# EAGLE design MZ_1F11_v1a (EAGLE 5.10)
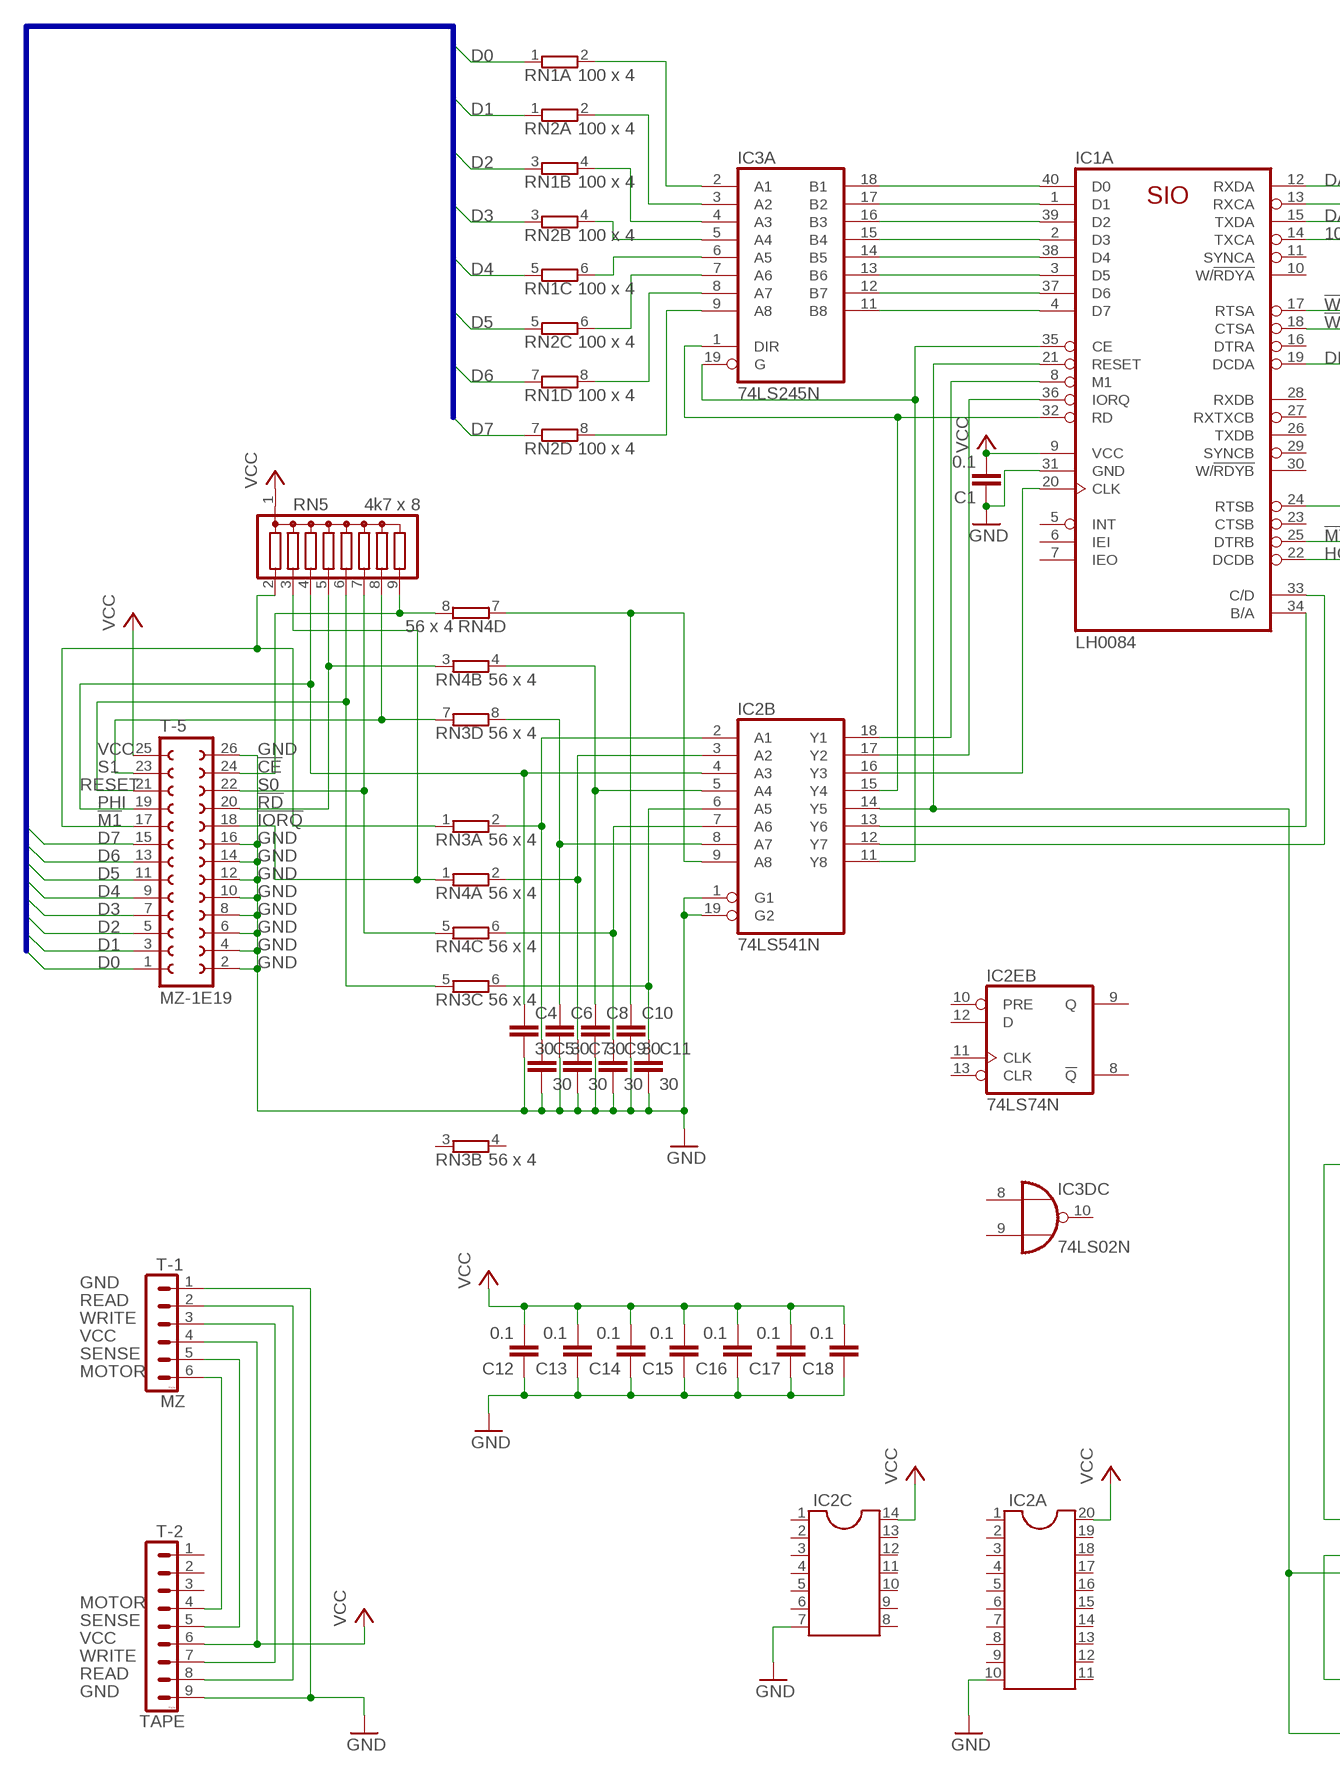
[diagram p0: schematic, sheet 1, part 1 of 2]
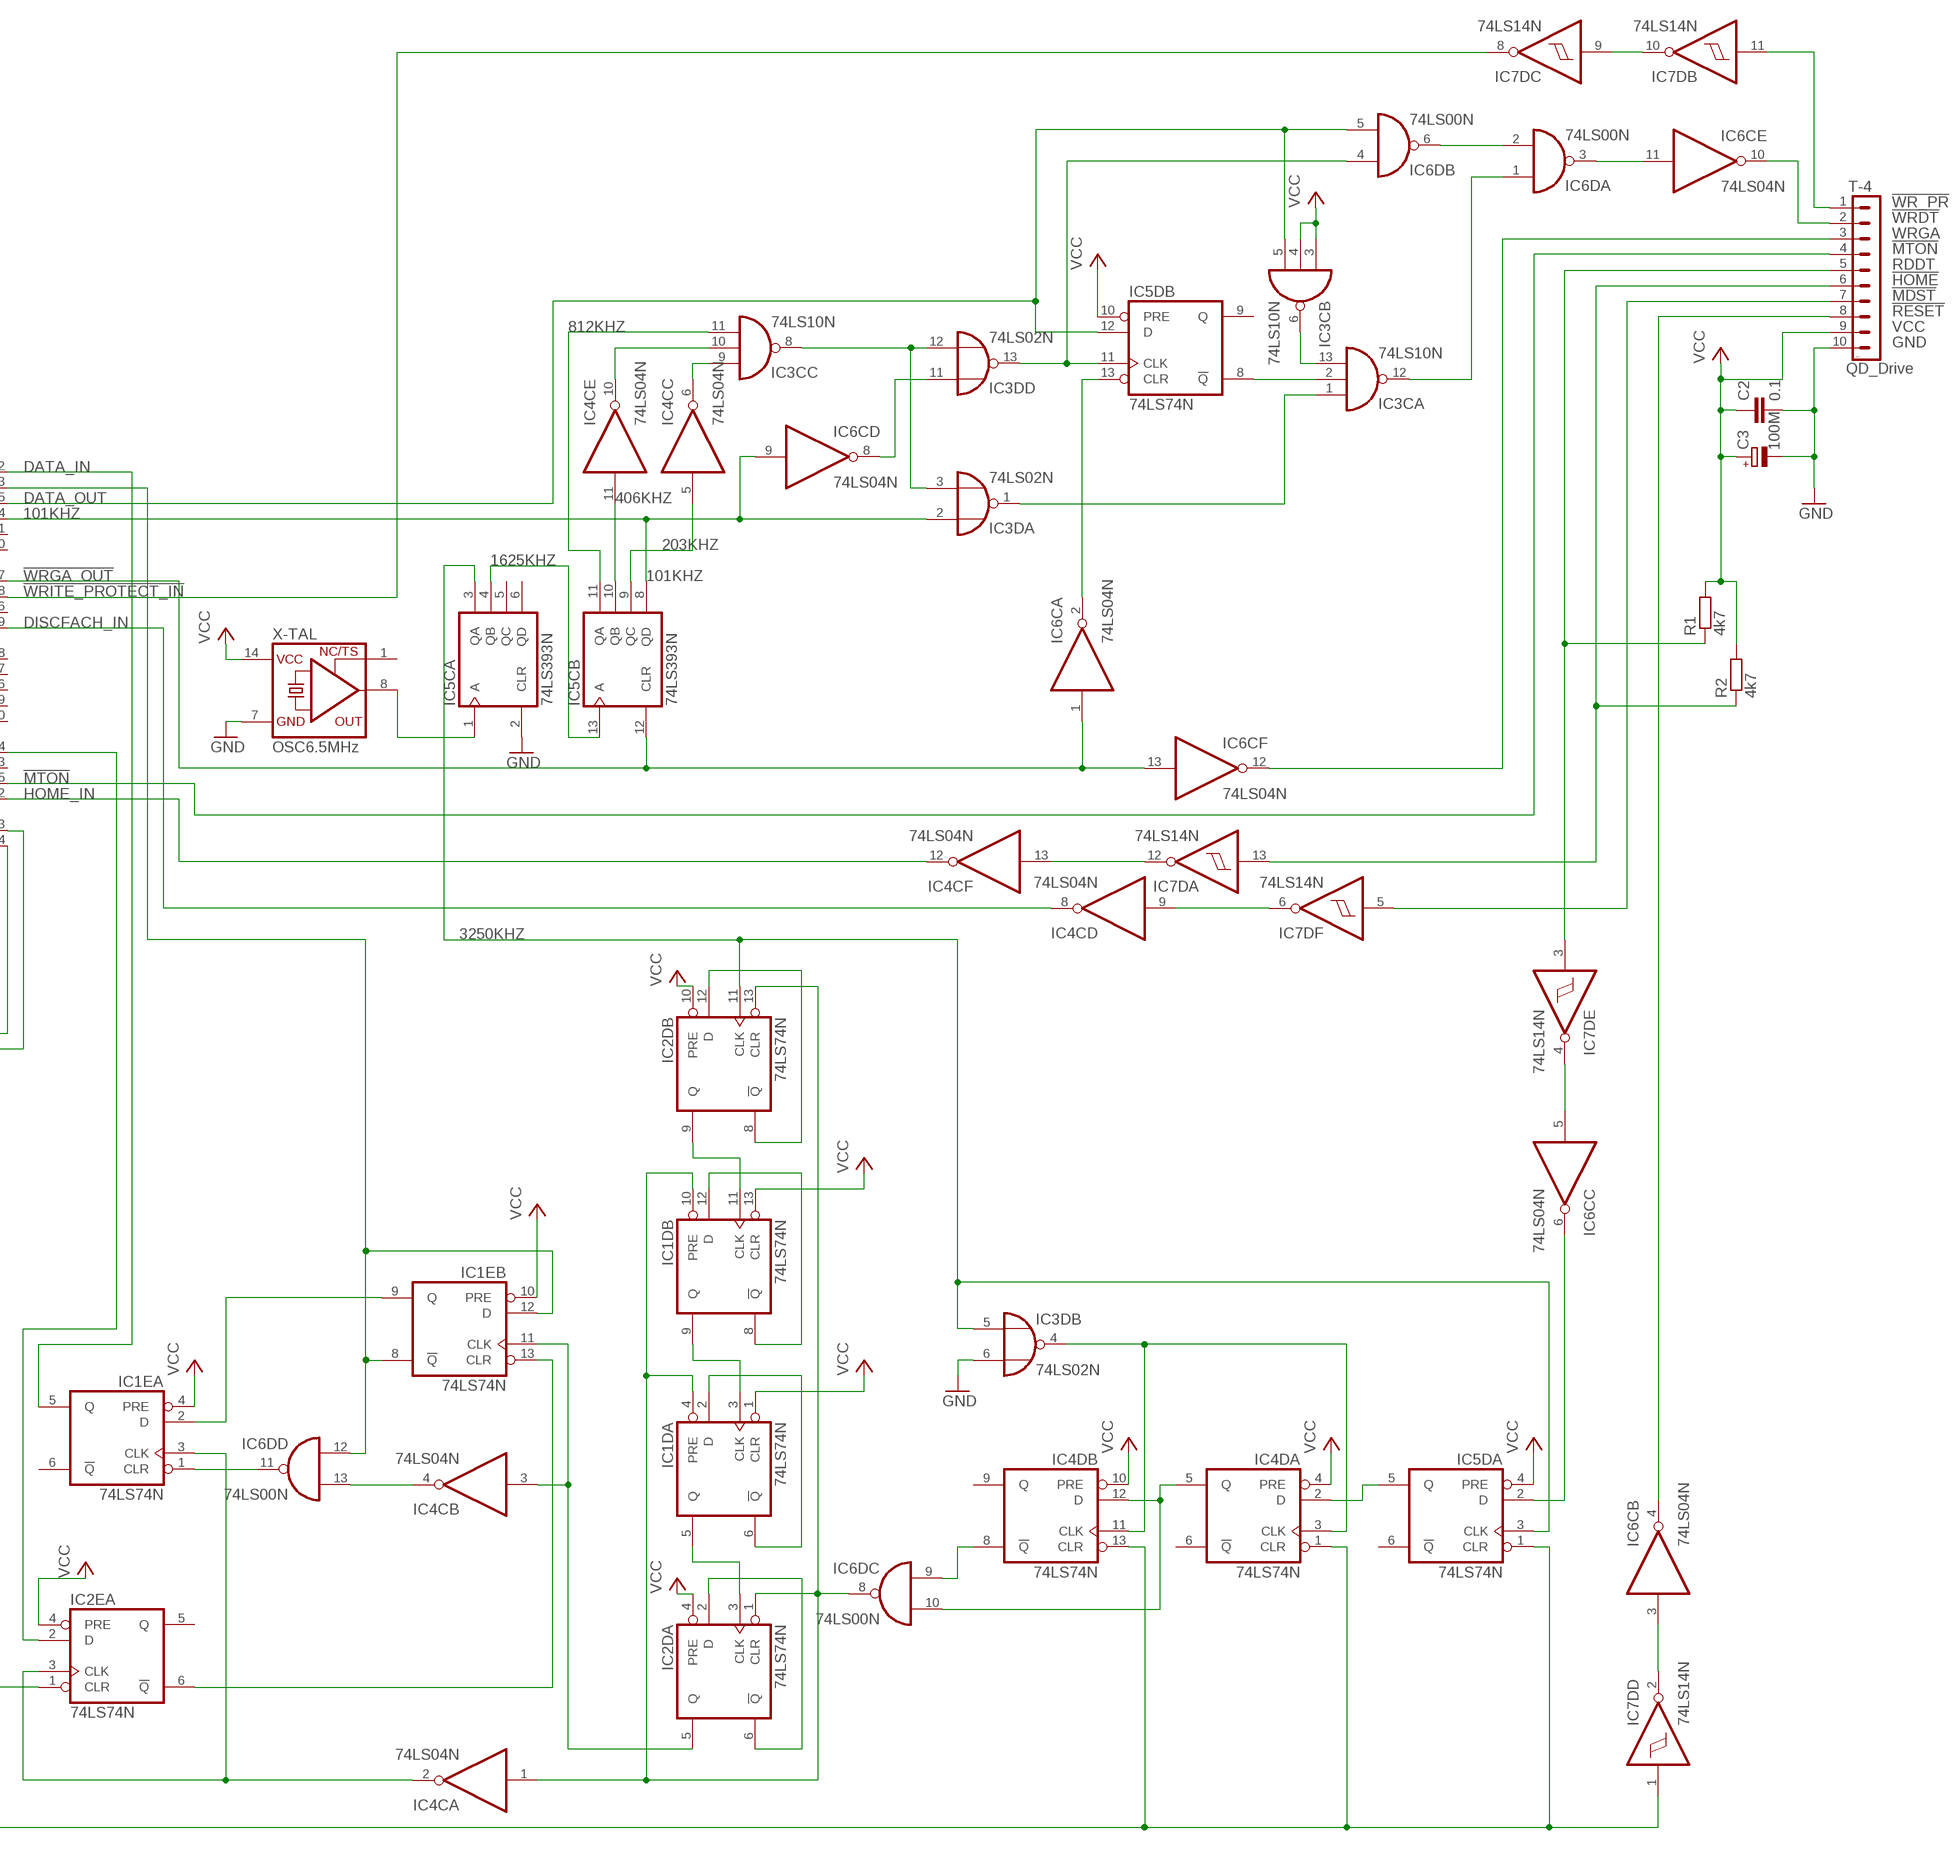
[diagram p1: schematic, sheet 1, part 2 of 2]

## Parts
C1  0.1  C-EU050-025X075  [C050-025X075]
C2  0.1  C-EU050-025X075  [C050-025X075]
C3  100M  CPOL-EUE2.5-5  [E2,5-5]
C4  30  C-EU050-025X075  [C050-025X075]
C5  30  C-EU050-025X075  [C050-025X075]
C6  30  C-EU050-025X075  [C050-025X075]
C7  30  C-EU050-025X075  [C050-025X075]
C8  30  C-EU050-025X075  [C050-025X075]
C9  30  C-EU050-025X075  [C050-025X075]
C10  30  C-EU050-025X075  [C050-025X075]
C11  30  C-EU050-025X075  [C050-025X075]
C12  0.1  C-EU050-025X075  [C050-025X075]
C13  0.1  C-EU050-025X075  [C050-025X075]
C14  0.1  C-EU050-025X075  [C050-025X075]
C15  0.1  C-EU050-025X075  [C050-025X075]
C16  0.1  C-EU050-025X075  [C050-025X075]
C17  0.1  C-EU050-025X075  [C050-025X075]
C18  0.1  C-EU050-025X075  [C050-025X075]
IC1A  LH0084  Z80SIO  [DIL40]
IC1D  74LS74N  [DIL14]
IC1E  74LS74N  [DIL14]
IC2A  DIL20  [DIL20]
IC2B  74LS541N  [DIL20]
IC2C  DIL14  [DIL14]
IC2D  74LS74N  [DIL14]
IC2E  74LS74N  [DIL14]
IC3A  74LS245N  [DIL20]
IC3C  74LS10N  [DIL14]
IC3D  74LS02N  [DIL14]
IC4C  74LS04N  [DIL14]
IC4D  74LS74N  [DIL14]
IC5C  74LS393N  [DIL14]
IC5D  74LS74N  [DIL14]
IC6C  74LS04N  [DIL14]
IC6D  74LS00N  [DIL14]
IC7D  74LS14N  [DIL14]
R1  4k7  R-EU_0207/10  [0207/10]
R2  4k7  R-EU_0207/10  [0207/10]
RN1  100 x 4  E4R  [SIL8]
RN2  100 x 4  E4R  [SIL8]
RN3  56 x 4  E4R  [SIL8]
RN4  56 x 4  E4R  [SIL8]
RN5  4k7 x 8  G08R  [SIL9]
T-1  MZ  PSH02-06P  [PSH02-06P]
T-2  TAPE  PSH02-09P  [PSH02-09P]
T-4  QD_Drive  PSH02-10P  [PSH02-10P]
T-5  MZ-1E19  FE13-2  [FE13-2]
X-TAL  OSC6.5MHz  XO-14  [DIL14S]

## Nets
101KHZ: IC1A.14(TXCA) IC3D.2(A:I0) IC5C.8(B:QD) IC6C.9(D:I)
203KHZ: IC4C.5(C:I) IC5C.9(B:QC)
406KHZ: IC4C.11(E:I) IC5C.10(B:QB)
812KHZ: IC3C.11(C:I2) IC5C.11(B:QA)
1625KHZ: IC5C.4(A:QB) IC5C.13(B:A)
3250KHZ: IC2D.11(B:CLK) IC3D.5(B:I0) IC5C.3(A:QA) IC5D.3(A:CLK)
6500KHZ: IC5C.1(A:A) X-TAL.8(OUT)
!CE: RN4.8 RN5.9 T-5.24
!HOME: IC7D.13(A:I) R2.1 T-4.6
!IORQ: RN4.1 RN5.3 T-5.18
!M1: RN3.1 RN5.2 T-5.17
!MDST: IC7D.5(F:I) T-4.7
!MTON: IC1A.25(DTRB) T-4.4
!RD: RN4.3 RN5.5 T-5.20
!RESET: IC6C.4(B:O) T-4.8
!WR_PR: IC7D.11(B:I) T-4.1
!WRDT: IC6C.10(E:O) T-4.2
!WRGA_OUT: IC1A.17(RTSA) IC5C.12(B:CLR) IC6C.1(A:I) IC6C.13(F:I)
!WRITE_PROTECT_IN: IC1A.18(CTSA) IC7D.8(C:O)
D0: RN1.1 T-5.1
D1: RN2.1 T-5.3
D2: RN1.3 T-5.5
D3: RN2.3 T-5.7
D4: RN1.5 T-5.9
D5: RN2.5 T-5.11
D6: RN1.7 T-5.13
D7: RN2.7 T-5.15
DATA_IN: IC1A.12(RXDA) IC1E.5(A:Q)
DATA_OUT: IC1A.15(TXDA) IC3C.5(B:I2) IC5D.12(B:D) IC6D.5(B:I1)
DISCFACH_IN: IC1A.19(DCDA) IC4C.8(D:O)
GND [power]: C1.1 C2.2 C3.- C4.2 C5.2 C6.2 C7.2 C8.2 C9.2 C10.2 C11.2 C12.1 C13.1 C14.1 C15.1 C16.1 C17.1 C18.1 IC1A.31(GND) IC2A.10 IC2B.1(G1) IC2B.19(G2) IC2C.7 IC3D.6(B:I1) IC5C.2(A:CLR) T-1.1 T-2.9 T-4.10 T-5.2 T-5.4 T-5.6 T-5.8 T-5.10 T-5.12 T-5.14 T-5.16 T-5.26 X-TAL.7(GND)
HOME_IN: IC1A.22(DCDB) IC4C.12(F:O)
MOTOR: T-1.6 T-2.4
N$1: IC1A.4(D7) IC3A.11(B8)
N$2: IC1A.37(D6) IC3A.12(B7)
N$3: IC1A.3(D5) IC3A.13(B6)
N$4: IC1A.38(D4) IC3A.14(B5)
N$5: IC1A.2(D3) IC3A.15(B4)
N$6: IC1A.39(D2) IC3A.16(B3)
N$7: IC1A.1(D1) IC3A.17(B2)
N$8: IC1A.40(D0) IC3A.18(B1)
N$9: IC1A.34(B/A) IC2B.13(Y6)
N$10: IC1A.32(RD) IC2B.15(Y4) IC3A.1(DIR)
N$11: C9.1 IC2B.7(A6) RN4.6
N$13: IC1A.33(C/D) IC2B.12(Y7)
N$15: IC1A.20(CLK) IC2B.16(Y3)
N$16: IC1A.8(M1) IC2B.18(Y1)
N$17: IC1A.36(IORQ) IC2B.17(Y2)
N$18: IC1A.21(RESET) IC2B.14(Y5) IC2E.1(A:CLR) IC4D.1(A:CLR) IC4D.13(B:CLR) IC5D.1(A:CLR) IC7D.1(D:I)
N$20: IC3D.11(D:I0) IC6C.8(D:O)
N$23: IC3C.9(C:I0) IC4C.6(C:O)
N$24: IC3C.10(C:I1) IC4C.10(E:O)
N$26: IC3C.8(C:O) IC3D.3(A:I1) IC3D.12(D:I1)
N$27: IC5D.13(B:CLR) IC6C.2(A:O)
N$28: IC3D.13(D:O) IC5D.11(B:CLK) IC6D.4(B:I0)
N$30: IC6D.2(A:I1) IC6D.6(B:O)
N$32: IC3C.2(A:I1) IC5D.8(B:!Q)
N$33: IC3C.6(B:O) IC3C.13(A:I2)
N$34: IC3C.1(A:I0) IC3D.1(A:O)
N$35: IC3C.12(A:O) IC6D.1(A:I0)
N$36: IC6C.11(E:I) IC6D.3(A:O)
N$37: IC7D.9(C:I) IC7D.10(B:O)
N$45: IC4C.9(D:I) IC7D.6(F:O)
N$46: IC4C.13(F:I) IC7D.12(A:O)
N$49: IC1E.1(A:CLR) IC6D.11(D:O)
N$50: IC4C.4(B:O) IC6D.13(D:I1)
N$51: IC1A.13(RXCA) IC1E.8(B:!Q) IC1E.12(B:D) IC6D.12(D:I0)
N$52: IC1E.2(A:D) IC1E.9(B:Q)
N$53: IC1D.5(A:Q) IC2D.3(A:CLK)
N$54: IC2D.2(A:D) IC2D.6(A:!Q)
N$55: IC1D.2(A:D) IC1D.6(A:!Q)
N$56: IC1D.8(B:!Q) IC1D.12(B:D)
N$57: IC2D.8(B:!Q) IC2D.12(B:D)
N$58: IC1D.11(B:CLK) IC2D.9(B:Q)
N$59: IC1D.3(A:CLK) IC1D.9(B:Q)
N$60: IC1E.13(B:CLR) IC2E.6(A:!Q)
N$61: IC1E.11(B:CLK) IC2D.5(A:Q) IC4C.3(B:I)
N$63: IC4D.5(A:Q) IC4D.12(B:D) IC6D.10(C:I1)
N$64: IC4D.2(A:D) IC5D.5(A:Q)
N$65: IC1D.4(A:PRE) IC1D.10(B:PRE) IC2D.1(A:CLR) IC2D.13(B:CLR) IC4C.1(A:I) IC6D.8(C:O)
N$66: IC3A.9(A8) RN2.8
N$67: IC1E.3(A:CLK) IC2E.3(A:CLK) IC4C.2(A:O)
N$70: IC1A.24(RTSB) IC2E.2(A:D)
N$71: IC3D.4(B:O) IC4D.3(A:CLK) IC4D.11(B:CLK)
N$72: IC6C.5(C:I) IC7D.4(E:O)
N$73: IC5D.2(A:D) IC6C.6(C:O)
N$74: IC4D.8(B:!Q) IC6D.9(C:I0)
N$76: IC3A.8(A7) RN1.8
N$77: IC3A.7(A6) RN2.6
N$78: IC3A.6(A5) RN1.6
N$79: IC6C.3(B:I) IC7D.2(D:O)
N$80: IC3A.5(A4) RN2.4
N$81: IC3A.4(A3) RN1.4
N$82: IC3A.3(A2) RN2.2
N$83: IC3A.2(A1) RN1.2
N$84: C11.1 IC2B.6(A5) RN3.6
N$85: C10.1 IC2B.9(A8) RN4.7
N$87: C8.1 IC2B.5(A4) RN4.4
N$88: C7.1 IC2B.3(A2) RN4.2
N$89: C6.1 IC2B.8(A7) RN3.8
N$90: C5.1 IC2B.2(A1) RN3.2
N$101: IC1A.35(CE) IC2B.11(Y8) IC3A.19(G)
PHI: C4.1 IC2B.4(A3) RN5.4 T-5.19
RDDT: IC7D.3(E:I) R1.1 T-4.5
READ: T-1.2 T-2.8
RESET: RN3.5 RN5.6 T-5.21
S0: RN4.5 RN5.7 T-5.22
S1: RN3.7 RN5.8 T-5.23
SENSE: T-1.5 T-2.5
VCC [power]: C1.2 C2.1 C3.+ C12.2 C13.2 C14.2 C15.2 C16.2 C17.2 C18.2 IC1A.9(VCC) IC1D.1(A:CLR) IC1D.13(B:CLR) IC1E.4(A:PRE) IC1E.10(B:PRE) IC2A.20 IC2C.14 IC2D.4(A:PRE) IC2D.10(B:PRE) IC2E.4(A:PRE) IC3C.3(B:I0) IC3C.4(B:I1) IC4D.4(A:PRE) IC4D.10(B:PRE) IC5D.4(A:PRE) IC5D.10(B:PRE) R1.2 R2.2 RN5.1 T-1.4 T-2.6 T-4.9 T-5.25 X-TAL.14(VCC)
WRGA: IC6C.12(F:O) T-4.3
WRITE: T-1.3 T-2.7
Unconnected: IC1A.5(INT) IC1A.6(IEI) IC1A.7(IEO) IC1A.10(W/!RDYA) IC1A.11(SYNCA) IC1A.16(DTRA) IC1A.23(CTSB) IC1A.26(TXDB) IC1A.27(RXTXCB) IC1A.28(RXDB) IC1A.29(SYNCB) IC1A.30(W/!RDYB) IC1E.6(A:!Q) IC2A.1 IC2A.2 IC2A.3 IC2A.4 IC2A.5 IC2A.6 IC2A.7 IC2A.8 IC2A.9 IC2A.11 IC2A.12 IC2A.13 IC2A.14 IC2A.15 IC2A.16 IC2A.17 IC2A.18 IC2A.19 IC2C.1 IC2C.2 IC2C.3 IC2C.4 IC2C.5 IC2C.6 IC2C.8 IC2C.9 IC2C.10 IC2C.11 IC2C.12 IC2C.13 IC2E.5(A:Q) IC2E.8(B:!Q) IC2E.9(B:Q) IC2E.10(B:PRE) IC2E.11(B:CLK) IC2E.12(B:D) IC2E.13(B:CLR) IC3D.8(C:I0) IC3D.9(C:I1) IC3D.10(C:O) IC4D.6(A:!Q) IC4D.9(B:Q) IC5C.5(A:QC) IC5C.6(A:QD) IC5D.6(A:!Q) IC5D.9(B:Q) RN3.3 RN3.4 T-2.1 T-2.2 T-2.3 X-TAL.1(TS)

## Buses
D[0..7]

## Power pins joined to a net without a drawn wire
GND: IC1D.7(P:GND) IC1E.7(P:GND) IC2B.10(GND) IC2D.7(P:GND) IC2E.7(P:GND) IC3A.10(GND) IC3C.7(P:GND) IC3D.7(P:GND) IC4C.7(P:GND) IC4D.7(P:GND) IC5C.7(P:GND) IC5D.7(P:GND) IC6C.7(P:GND) IC6D.7(P:GND) IC7D.7(P:GND)
VCC: IC1D.14(P:VCC) IC1E.14(P:VCC) IC2B.20(VCC) IC2D.14(P:VCC) IC2E.14(P:VCC) IC3A.20(VCC) IC3C.14(P:VCC) IC3D.14(P:VCC) IC4C.14(P:VCC) IC4D.14(P:VCC) IC5C.14(P:VCC) IC5D.14(P:VCC) IC6C.14(P:VCC) IC6D.14(P:VCC) IC7D.14(P:VCC)

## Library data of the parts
C1 C2 C12-C18 = EC_rcl_VP:C-EU: CAPACITOR, European symbol
C3 = EC_rcl_VP:CPOL-EU: POLARIZED CAPACITOR, European symbol
C4-C11 = resistor:C-EU: CAPACITOR, European symbol
IC1A = EC_zilog_MP:Z80SIO: Z80 FAMILY DEVICE
IC1D IC1E IC2D IC2E IC4D IC5D = EC_74xx-eu_MP:74*74: Dual D type positive edge triggered FLIP FLOP, preset and clear
IC2A = EC_ic-package_MP:DIL20: Dual In Line
IC2B = EC_74xx-eu_MP:74*541: Octal BUFFER and LINE DRIVER, 3-state
IC2C = EC_ic-package_MP:DIL14: Dual In Line
IC3A = EC_74xx-eu_MP:74*245: Octal BUS TRANSCEIVER, 3-state
IC3C = EC_74xx-eu_MP:74*10: Triple 3-input NAND gate
IC3D = EC_74xx-eu_MP:74*02: Quad 2-input NOR gate
IC4C IC6C = EC_74xx-eu_MP:74*04: Hex INVERTER
IC5C = EC_74xx-eu_MP:74*393: Dual 4-bit decade and binary COUNTER
IC6D = EC_74xx-eu_MP:74*00: Quad 2-input NAND gate
IC7D = EC_74xx-eu_MP:74*14: Hex schmitt trigger INVERTER
R1 R2 = rcl:R-EU_: RESISTOR, European symbol
RN1-RN4 = resistor-sil:E4R: SIL RESISTOR
RN5 = resistor-sil:G08R: SIL RESISTOR
T-1 = #PaJa_konektory:PSH02-06: Konektory se zamkem - vidlice - 6pin
T-2 = #PaJa_konektory:PSH02-09: Konektory se zamkem - vidlice - 9pin
T-4 = #PaJa_konektory:PSH02-10: Konektory se zamkem - vidlice - 10pin
T-5 = sharp:FE13-2: FEMALE HEADER
X-TAL = EC_crystal_U:XO-: CRYSTAL

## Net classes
0 default: width 0.356 mm, drill 0.254 mm, clearance 0.254 mm
1 power: width 0.508 mm, drill 0.508 mm, clearance 0.254 mm

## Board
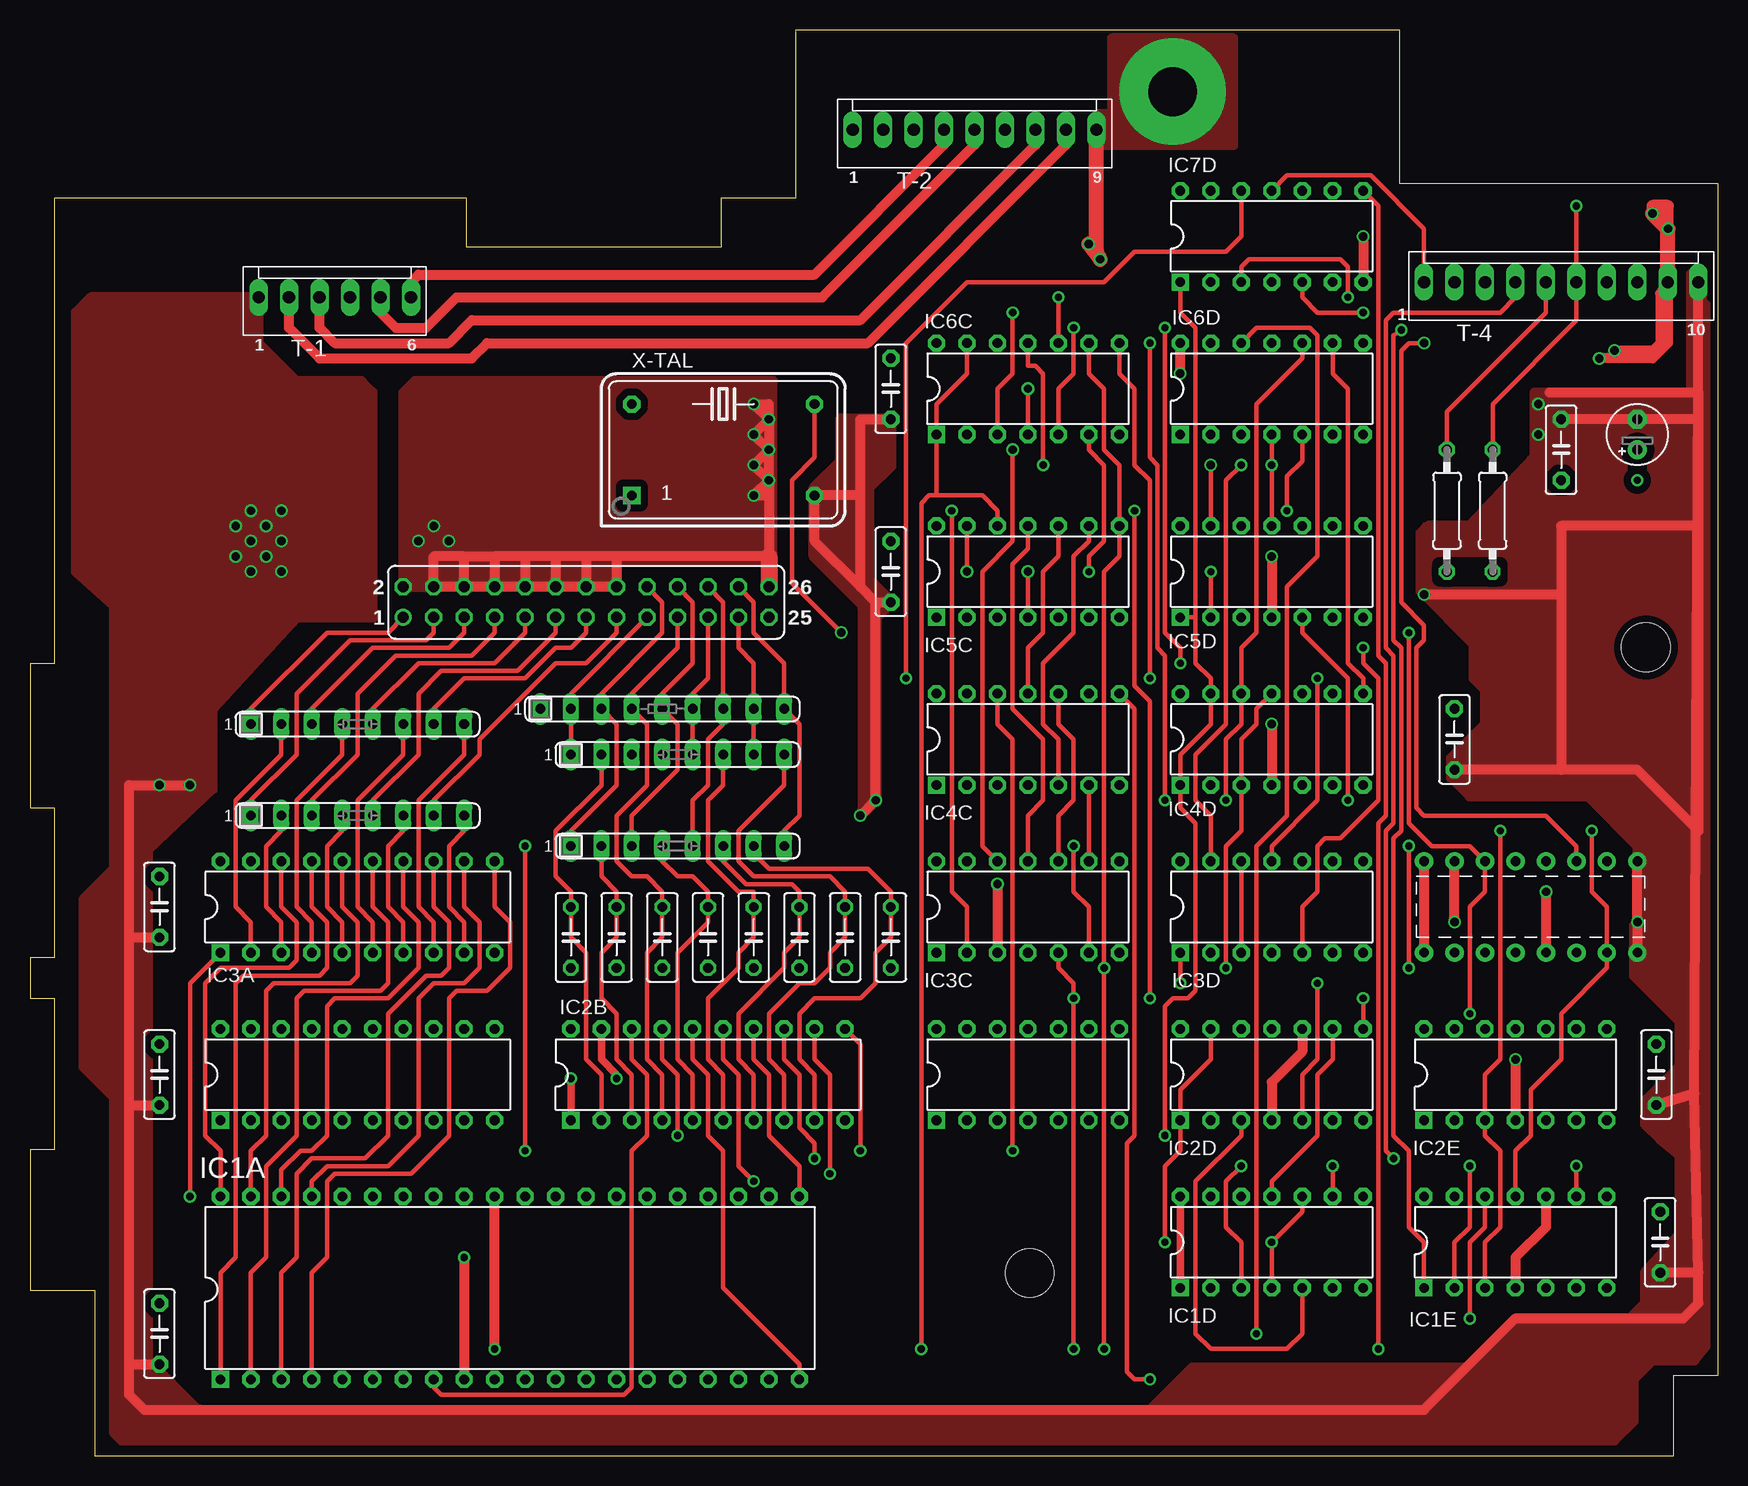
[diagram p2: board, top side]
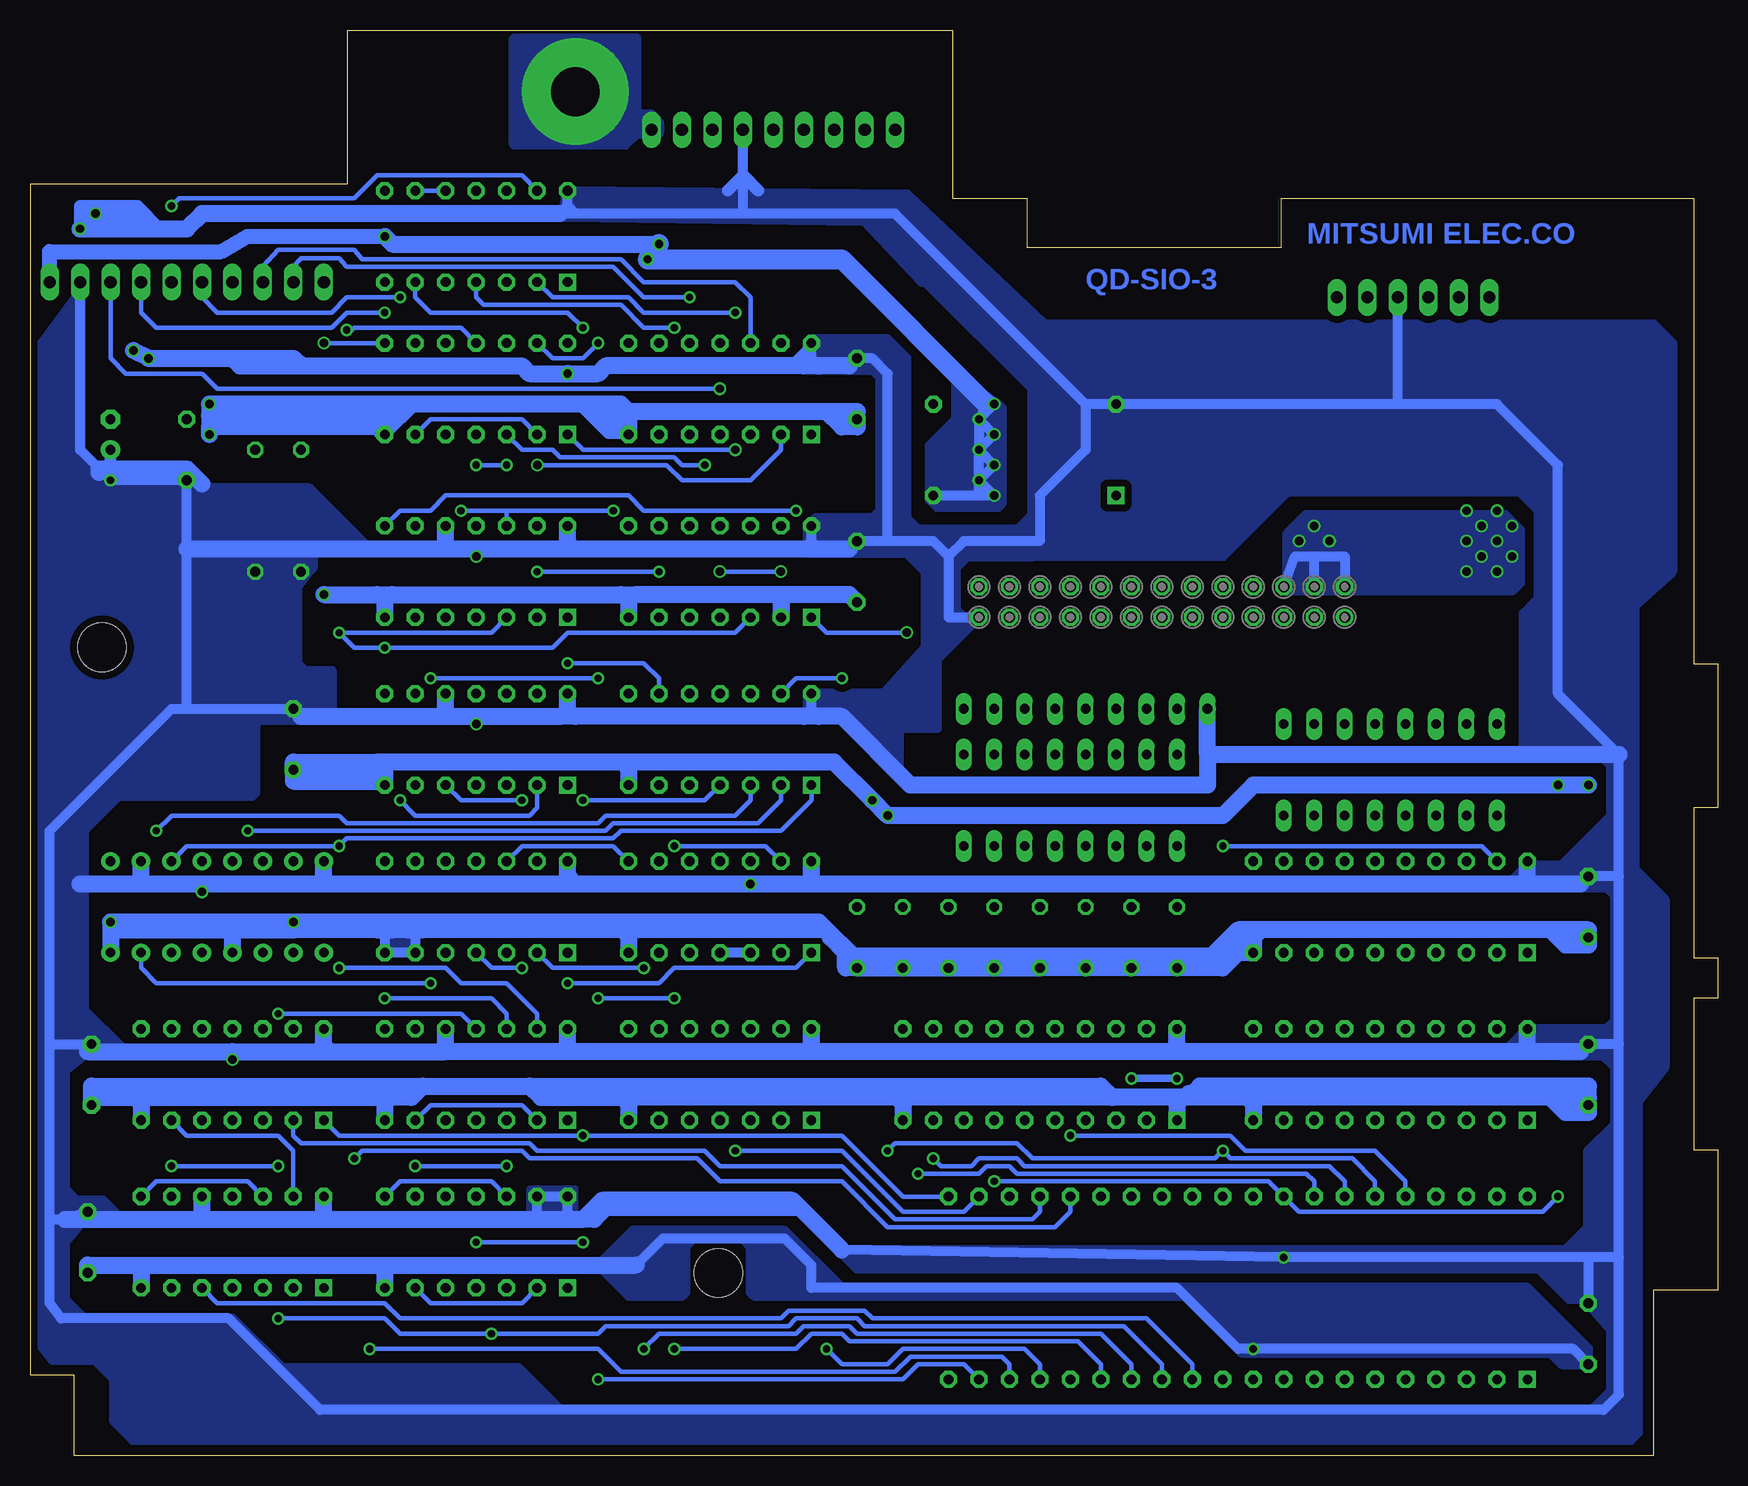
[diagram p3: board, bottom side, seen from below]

Size 140.7 x 118.8 mm. Coordinates in mm from the lower left corner, seen from the top.
Outline: 5.4,0 137,0 137,6.7 140.7,6.7 140.7,106 114.2,106 114.2,118.8 63.8,118.8 63.8,104.8 57.6,104.8 57.6,100.7 36.4,100.7 36.4,104.8 2,104.8 2,66 0,66 0,54 2,54 2,41.5 0,41.5 0,38.1 2,38.1 2,25.5 0,25.5 0,13.8 5.4,13.8 5.4,0
Copper layers (1*16): Top 0.035mm / dielectric 1.5mm / Bottom 0.035mm
Design rules "quickdisk1": minimum track width 6mil, minimum drill 12mil, track to track 8mil, track to pad 8mil, pad to pad 8mil, via to via 8mil, smd to smd 0mil, copper to edge 10mil, drill to drill 10mil, minimum pad ring 10mil, minimum via ring 6mil, stop-mask expansion 2mil, vias tented up to drill 100mil, thermal gap 10mil
Holes 4 mm at 83.33,15.22
Holes 4.06 mm at 134.7,67.35
tRestrict: area 117.5,73 to 122.6,74.3

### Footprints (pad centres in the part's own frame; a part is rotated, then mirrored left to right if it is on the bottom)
C050-025X075 = drill 0.813 pad 1.422 octagon: 1 -2.54,0; 2 2.54,0
E2,5-5 = drill 0.813 pad 1.6 round: + -1.27,0 | drill 0.813 pad 1.6 octagon: - 1.27,0
C050-025X075' = drill 0.813 octagon: 1 -2.54,0; 2 2.54,0
DIL40 = drill 0.813 pad 1.422 square: 1 -24.13,-7.62 | drill 0.813 pad 1.422 octagon: 2 -21.59,-7.62; 3 -19.05,-7.62; 4 -16.51,-7.62; 5 -13.97,-7.62; 6 -11.43,-7.62; 7 -8.89,-7.62; 8 -6.35,-7.62; 9 -3.81,-7.62; 10 -1.27,-7.62; 11 1.27,-7.62; 12 3.81,-7.62; 13 6.35,-7.62; 14 8.89,-7.62; 15 11.43,-7.62; 16 13.97,-7.62; 17 16.51,-7.62; 18 19.05,-7.62; 19 21.59,-7.62; 20 24.13,-7.62; 21 24.13,7.62; 22 21.59,7.62; 23 19.05,7.62; 24 16.51,7.62; 25 13.97,7.62; 26 11.43,7.62; 27 8.89,7.62; 28 6.35,7.62; 29 3.81,7.62; 30 1.27,7.62; 31 -1.27,7.62; 32 -3.81,7.62; 33 -6.35,7.62; 34 -8.89,7.62; 35 -11.43,7.62; 36 -13.97,7.62; 37 -16.51,7.62; 38 -19.05,7.62; 39 -21.59,7.62; 40 -24.13,7.62
DIL14 = drill 0.813 pad 1.422 square: 1 -7.62,-3.81 | drill 0.813 pad 1.422 octagon: 2 -5.08,-3.81; 3 -2.54,-3.81; 4 0,-3.81; 5 2.54,-3.81; 6 5.08,-3.81; 7 7.62,-3.81; 8 7.62,3.81; 9 5.08,3.81; 10 2.54,3.81; 11 0,3.81; 12 -2.54,3.81; 13 -5.08,3.81; 14 -7.62,3.81
DIL20 = drill 0.813 pad 1.422 square: 1 -11.43,-3.81 | drill 0.813 pad 1.422 octagon: 2 -8.89,-3.81; 3 -6.35,-3.81; 4 -3.81,-3.81; 5 -1.27,-3.81; 6 1.27,-3.81; 7 3.81,-3.81; 8 6.35,-3.81; 9 8.89,-3.81; 10 11.43,-3.81; 11 11.43,3.81; 12 8.89,3.81; 13 6.35,3.81; 14 3.81,3.81; 15 1.27,3.81; 16 -1.27,3.81; 17 -3.81,3.81; 18 -6.35,3.81; 19 -8.89,3.81; 20 -11.43,3.81
0207/10 = drill 0.813 octagon: 1 -5.08,0; 2 5.08,0
SIL8 = drill 0.813 long: 1 -8.89,0; 2 -6.35,0; 3 -3.81,0; 4 -1.27,0; 5 1.27,0; 6 3.81,0; 7 6.35,0; 8 8.89,0
SIL9 = drill 0.813 long: 1 -10.16,0; 2 -7.62,0; 3 -5.08,0; 4 -2.54,0; 5 0,0; 6 2.54,0; 7 5.08,0; 8 7.62,0; 9 10.16,0
PSH02-06P = drill 1.016 pad 1.422 long: 1 -6.35,0; 2 -3.81,0; 3 -1.27,0; 4 1.27,0; 5 3.81,0; 6 6.35,0
PSH02-09P = drill 1.016 pad 1.422 long: 1 -10.16,0; 2 -7.62,0; 3 -5.08,0; 4 -2.54,0; 5 0,0; 6 2.54,0; 7 5.08,0; 8 7.62,0; 9 10.16,0
PSH02-10P = drill 1.016 pad 1.422 long: 1 -11.43,0; 2 -8.89,0; 3 -6.35,0; 4 -3.81,0; 5 -1.27,0; 6 1.27,0; 7 3.81,0; 8 6.35,0; 9 8.89,0; 10 11.43,0
FE13-2 = drill 0.914 round: 1 -15.24,1.27 | drill 0.914 octagon: 2 -15.24,-1.27; 3 -12.7,1.27; 4 -12.7,-1.27; 5 -10.16,1.27; 6 -10.16,-1.27; 7 -7.62,1.27; 8 -7.62,-1.27; 9 -5.08,1.27; 10 -5.08,-1.27; 11 -2.54,1.27; 12 -2.54,-1.27; 13 0,1.27; 14 0,-1.27; 15 2.54,1.27; 16 2.54,-1.27; 17 5.08,1.27; 18 5.08,-1.27; 19 7.62,1.27; 20 7.62,-1.27; 21 10.16,1.27; 22 10.16,-1.27; 23 12.7,1.27; 24 12.7,-1.27; 25 15.24,1.27; 26 15.24,-1.27
DIL14S = drill 0.813 pad 1.422 square: 1 -7.62,-3.81 | drill 0.813 pad 1.422 octagon: 7 7.62,-3.81; 8 7.62,3.81; 14 -7.62,3.81

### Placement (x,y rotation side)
C1  10.79,10.16 90 top
C2  127.64,83.82 90 top
C3  133.99,85.09 90 top
C4  30  [C050-025X075']  52.7,43.18 270 top
C5  30  [C050-025X075']  45.09,43.18 270 top
C6  30  [C050-025X075']  67.94,43.18 270 top
C7  30  [C050-025X075']  48.9,43.18 270 top
C8  30  [C050-025X075']  56.52,43.18 270 top
C9  30  [C050-025X075']  64.14,43.18 270 top
C10  30  [C050-025X075']  71.75,43.18 270 top
C11  30  [C050-025X075']  60.33,43.18 270 top
C12  10.79,31.75 90 top
C13  10.79,45.72 90 top
C14  135.89,17.78 90 top
C15  135.57,31.75 90 top
C16  118.75,59.69 90 top
C17  71.75,73.66 90 top
C18  71.75,88.9 90 top
IC1A  40.01,13.97 0 top
IC1D  103.5,17.78 0 top
IC1E  123.83,17.78 0 top
IC2A  27.3,31.75 0 top
IC2B  56.52,31.75 0 top
IC2C  83.19,31.75 0 top
IC2D  103.5,31.75 0 top
IC2E  123.83,31.75 0 top
IC3A  27.3,45.72 0 top
IC3C  83.19,45.72 0 top
IC3D  103.5,45.72 0 top
IC4C  83.19,59.69 0 top
IC4D  103.5,59.69 0 top
IC5C  83.19,73.66 0 top
IC5D  103.5,73.66 0 top
IC6C  83.19,88.9 0 top
IC6D  103.5,88.9 0 top
IC7D  103.5,101.6 0 top
R1  118.11,78.74 270 top
R2  121.92,78.74 270 top
RN1  27.3,60.96 0 top
RN2  27.3,53.34 0 top
RN3  53.98,58.42 0 top
RN4  53.98,50.8 0 top
RN5  52.7,62.23 0 top
T-1  25.4,96.52 0 top
T-2  78.74,110.49 0 top
T-4  127.64,97.79 0 top
T-5  46.35,71.12 180 bottom
X-TAL  57.78,83.82 0 top

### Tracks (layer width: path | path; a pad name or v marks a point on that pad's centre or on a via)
101KHZ  (via drill 0.6 pad 1.02)
  Top 0.356: v89.53,8.89 v89.53,40.64 89.53,73.66 90.81,74.93 IC5C.8 90.81,82.55 89.53,83.82 89.53,88.9 88.27,90.17 IC6C.9
  Bottom 0.356: IC1A.14 48.9,7.62 51.44,10.16 71.75,10.16 72.39,10.79 76.2,10.79 76.83,10.16 88.27,10.16 v89.53,8.89 | IC3D.2 97.16,40.64 v89.53,40.64
203KHZ
  Top 0.356: IC4C.5 85.72,59.69 84.45,60.96 84.45,66.04 87,68.58 87,74.93 88.27,76.2 IC5C.9
406KHZ
  Top 0.356: IC4C.11 83.19,67.31 84.45,68.58 84.45,73.66 85.72,74.93 IC5C.10
812KHZ
  Top 0.356: IC3C.11 83.19,53.34 84.45,54.61 84.45,59.69 81.92,62.23 81.92,74.3 83.19,75.56 IC5C.11
1625KHZ  (via drill 0.7 pad 1.02)
  Top 0.356: IC5C.4 v83.19,73.66 | v78.11,73.66 IC5C.13
  Bottom 0.356: v83.19,73.66 v78.11,73.66
3250KHZ  (via drill 0.6 pad 1.02, 0.8 pad 1.52)
  Top 0.356: v120.02,36.83 120.02,45.72 121.28,46.99 v121.28,49.53 120.02,50.8 116.84,50.8 114.94,52.7 v114.94,68.58 | v111.12,67.31 111.12,66.04 112.39,64.77 112.39,54.61 109.22,51.44 107.95,51.44 107.31,50.8 107.31,46.99 106.05,45.72 IC3D.5
  Bottom 0.356: IC2D.11 104.78,36.83 v120.02,36.83 | IC5D.3 102.23,68.58 v114.94,68.58 113.67,67.31 v111.12,67.31 97.16,67.31 95.89,68.58 81.92,68.58 IC5C.3
6500KHZ  (via drill 0.7 pad 1.02)
  Top 0.356: v67.63,68.58 63.5,72.71 63.5,80.96 63.5,81.28 65.41,83.19 X-TAL.8
  Bottom 0.356: IC5C.1 74.3,68.58 v67.63,68.58
!CE
  Top 0.356: RN4.8 62.87,52.07 64.14,53.34 64.14,60.96 RN5.9 62.87,66.04 60.33,68.58 60.33,71.12 T-5.24
!HOME  (via drill 0.6 pad 1.02)
  Top 0.356: v128.91,104.14 T-4.6 128.91,94.61 121.92,87.63 R2.1
  Bottom 0.356: IC7D.13 99.69,106.68 111.76,106.68 113.67,104.78 128.27,104.78 v128.91,104.14
!IORQ
  Top 0.356: RN4.1 45.09,52.07 48.9,55.88 48.9,60.96 RN5.3 47.62,63.5 52.7,68.58 52.7,71.12 T-5.18
!M1
  Top 0.356: RN3.1 RN5.2 45.09,63.5 T-5.17
!MDST  (via drill 0.6 pad 1.02)
  Top 0.356: v111.12,95.25 107.31,95.25 106.05,96.52 IC7D.5
  Bottom 0.356: T-4.7 131.44,95.25 130.18,93.98 115.57,93.98 114.3,95.25 v111.12,95.25
!MTON  (via drill 0.6 pad 1.02)
  Top 0.356: v113.67,24.77 113.03,25.4 113.03,52.07 113.67,52.7 113.67,66.67 113.03,67.31 113.03,94.61 113.67,95.25 122.56,95.25 123.83,96.52 T-4.4
  Bottom 0.356: IC1A.25 53.98,20.32 55.24,19.05 69.22,19.05 73.03,22.86 83.19,22.86 85.09,24.77 99.06,24.77 99.69,25.4 113.03,25.4 v113.67,24.77
!RD
  Top 0.356: RN4.3 50.16,53.34 53.98,57.15 53.98,60.96 RN5.5 52.7,63.5 55.24,66.04 55.24,71.12 T-5.20
!RESET  (via drill 0.7 pad 1.02)
  Top 0.356: IC6C.4 v83.19,88.9
  Bottom 0.356: T-4.8 133.99,91.44 132.72,90.17 126.36,90.17 125.09,88.9 v83.19,88.9
!WR_PR
  Top 0.356: IC7D.11 104.78,106.68 111.76,106.68 116.2,102.23 T-4.1
!WRDT  (via drill 0.6 pad 1.02)
  Top 0.356: IC6C.10 v85.72,96.52
  Bottom 0.356: T-4.2 118.75,99.06 118.11,99.8 114.94,99.8 114.3,99.06 92.08,99.06 89.53,96.52 v85.72,96.52
!WRGA_OUT  (via drill 0.6 pad 1.02)
  Top 0.356: IC5C.12 80.64,78.74 79.38,80.01 75.56,80.01 | 75.56,80.01 74.93,80.01 74.3,79.38 74.3,79.06 v74.3,8.89 | 75.56,80.01 IC6C.1 75.56,87.63 78.11,90.17 IC6C.13
  Bottom 0.356: IC1A.17 56.52,7.62 57.78,8.89 67.94,8.89 69.22,7.62 73.03,7.62 v74.3,8.89
!WRITE_PROTECT_IN  (via drill 0.6 pad 1.02)
  Top 0.356: v112.39,8.89 112.39,52.7 113.03,53.34 113.03,66.04 112.39,66.67 112.39,104.14 IC7D.8
  Bottom 0.356: IC1A.18 59.05,7.62 59.69,8.26 67.31,8.26 68.58,6.99 91.44,6.99 93.34,8.89 v112.39,8.89
D0
  Top 0.356: RN1.1 18.41,62.23 24.77,68.58 29.84,68.58 T-5.1
D1
  Top 0.356: RN2.1 18.41,54.61 22.23,58.42 22.23,63.5 26.67,67.94 33.02,67.94 33.66,68.58 T-5.3
D2
  Top 0.356: RN1.3 23.5,62.23 28.57,67.31 34.92,67.31 36.2,68.58 T-5.5
D3
  Top 0.356: RN2.3 23.5,54.61 27.3,58.42 27.3,63.5 30.48,66.67 36.83,66.67 38.73,68.58 T-5.7
D4
  Top 0.356: RN1.5 28.57,62.23 32.38,66.04 38.73,66.04 41.27,68.58 T-5.9
D5
  Top 0.356: RN2.5 28.57,54.61 32.38,58.42 32.38,63.5 34.29,65.41 40.64,65.41 43.81,68.58 T-5.11
D6
  Top 0.356: RN1.7 33.66,62.23 36.2,64.77 41.27,64.77 43.81,67.31 45.09,67.31 46.35,68.58 T-5.13
D7
  Top 0.356: RN2.7 33.66,54.61 37.47,58.42 37.47,59.69 43.81,66.04 46.35,66.04 48.9,68.58 T-5.15
DATA_IN
  Bottom 0.356: IC1A.12 43.81,7.62 47.62,11.43 70.48,11.43 71.12,12.06 77.47,12.06 78.11,11.43 109.86,11.43 111.12,12.7 125.09,12.7 IC1E.5
DATA_OUT  (via drill 0.6 pad 1.02)
  Top 0.356: v87,8.89 v87,38.1 87,39.37 85.72,40.64 IC3C.5 | v93.34,38.1 93.34,62.87 92.08,64.14 v92.08,78.74 | v104.78,78.74 104.78,81.6 106.05,82.87 IC6D.5
  Bottom 0.356: IC1A.15 51.44,7.62 53.34,9.53 72.39,9.53 73.03,10.16 75.56,10.16 76.83,8.89 v87,8.89 | v87,38.1 v93.34,38.1 | v92.08,78.74 100.97,78.74 | 100.97,78.74 v104.78,78.74 | 100.97,78.74 IC5D.12
DISCFACH_IN  (via drill 0.6 pad 1.02)
  Top 0.356: v93.34,6.35 92.08,6.35 91.44,6.99 91.44,26.04 92.08,26.67 92.08,62.23 IC4C.8
  Bottom 0.356: IC1A.19 62.87,7.62 66.67,7.62 67.94,6.35 v93.34,6.35
GND  (via drill 0.6 pad 1.02, 0.7 pad 1.02, 0.8 pad 1.52, 4.06 pad 8.89)
  Top 0.61: IC2B.19 47.62,33.02 48.9,31.75 v48.9,31.43 | IC2B.1 v45.09,31.43
  Top 0.813: v38.73,8.89 IC1A.31 | v13.34,55.88 v10.79,55.88 8.26,55.88 8.26,43.18 | 8.26,43.18 C13.1 | 8.26,29.21 8.26,43.18 | 8.26,29.21 C12.1 | 8.26,7.62 8.26,29.21 | 8.26,7.62 C1.1 | 8.26,7.62 8.26,5.08 9.53,3.81 116.2,3.81 123.83,11.43 137.79,11.43 139.06,12.7 139.06,15.24 | 139.06,15.24 C14.1 | 139.06,15.24 138.75,30.16 | 138.75,30.16 C15.1 | 138.75,30.16 139.06,88.58 | 139.06,88.58 126.68,88.58 | 139.06,77.47 139.06,52.07 133.99,57.15 127.64,57.15 | 127.64,57.15 C16.1 | 127.64,71.75 127.64,57.15 | 127.64,71.75 127.64,77.47 139.06,77.47 | 139.06,86.36 139.06,77.47 | 139.06,88.58 139.06,86.36 | 139.06,88.58 T-4.10 | C2.2 C3.- 139.06,86.36 | 127.64,71.75 v116.2,71.75 | v69.22,53.34 v70.48,54.61 70.48,71.12 | 70.48,71.12 C17.1 | 70.48,71.12 69.22,72.39 | 69.22,72.39 69.22,80.01 | 69.22,80.01 69.22,86.36 C18.1 | 61.59,80.01 61.59,74.93 48.9,74.93 | 36.2,74.93 33.66,74.93 T-5.4 T-5.6 | 41.27,74.93 38.73,74.93 | 43.81,74.93 41.27,74.93 | 46.35,74.93 43.81,74.93 | 48.9,74.93 46.35,74.93 | 48.9,74.93 T-5.16 T-5.6 | 46.35,74.93 T-5.14 | 43.81,74.93 T-5.12 | 41.27,74.93 T-5.10 | T-5.6 36.2,74.93 | 38.73,74.93 T-5.8 | 61.59,80.01 v60.33,80.01 v61.59,81.28 | v61.59,81.28 v60.33,82.55 v61.59,83.82 | v61.59,83.82 v60.33,85.09 v61.59,86.36 | v61.59,86.36 v60.33,87.63 61.59,87.63 v61.59,86.36 | v61.59,86.36 v61.59,83.82 | v61.59,81.28 v61.59,83.82 | v61.59,81.28 61.59,80.01 | 69.22,72.39 65.41,76.2 X-TAL.7 69.22,80.01 | v118.75,44.45 v118.75,49.53 | v133.99,41.91 v133.99,44.45 v133.99,49.53 | v111.12,101.6 IC7D.7 | v89.22,99.69 88.9,100.33 | 36.2,74.93 38.73,74.93
  Top 1.27: 88.9,100.33 T-2.9 | v88.27,100.97 v89.22,99.69
  Top 1.422: 61.59,74.93 T-5.26
  Bottom 0.61: v45.09,31.43 v48.9,31.43
  Bottom 0.813: 45.72,29.84 45.09,29.21 44.45,29.84 | 67.31,29.84 67.94,29.21 68.58,29.84 | 39.37,29.84 38.73,29.21 38.1,29.84 | C1.1 12.06,8.89 v38.73,8.89 40.01,8.89 45.09,13.97 75.56,13.97 75.56,15.88 77.79,18.1 87.95,18.1 90.17,15.88 110.49,15.88 111.12,15.24 111.76,15.88 130.81,15.88 131.44,15.24 132.08,15.88 135.89,15.88 | 132.08,29.84 131.44,29.21 130.81,29.84 | 111.76,29.84 111.12,29.21 110.49,29.84 | 91.44,29.84 90.81,29.21 90.17,29.84 | 90.17,57.78 90.81,57.15 91.44,57.78 | 110.49,57.78 111.12,57.15 111.76,57.78 | 90.17,43.81 90.81,43.18 91.44,43.81 | 111.12,43.18 110.49,43.81 | 111.12,43.18 IC3D.7 IC3D.6 108.58,43.18 | 111.76,43.81 111.12,43.18 | v133.99,41.91 133.99,43.18 133.35,43.81 v133.99,44.45 | 110.49,71.75 111.12,71.12 111.76,71.75 | 91.44,71.75 90.81,71.12 90.17,71.75 | 90.17,87 90.81,86.36 90.81,87 | 109.86,87.63 111.12,86.36 111.12,85.41 | X-TAL.7 61.59,80.01 | 61.59,80.01 v61.59,81.28 | v61.59,81.28 v61.59,83.82 | v61.59,86.36 v61.59,83.82 | v61.59,86.36 60.96,87.63 v60.33,87.63 v61.59,86.36 | 72.07,41.59 C10.2 | 61.59,80.01 v60.33,80.01 v61.59,81.28 | v61.59,81.28 v60.33,82.55 v61.59,83.82 | v61.59,83.82 v60.33,85.09 v61.59,86.36 | T-5.2 31.11,74.93 33.66,74.93 | T-5.4 33.66,74.93 | T-5.6 35.24,74.93 33.66,74.93 | 108.58,43.18 107.95,43.81 109.22,43.81 108.58,43.18 | 118.75,43.81 v118.75,44.45
  Bottom 1.27: T-4.10 139.06,100.33 124.78,100.33 122.56,101.6 v111.12,101.6
  Bottom 1.422: 50.48,29.84 45.72,29.84 38.1,29.84 13.97,29.84 | 50.48,29.84 67.31,29.84 68.58,29.84 90.17,29.84 91.44,29.84 98.11,29.84 99.06,30.8 | 67.94,29.21 IC2B.10 | 45.09,29.21 IC2B.1 | 39.37,29.84 44.45,29.84 | 38.73,29.21 IC2A.10 | 10.79,29.84 13.97,29.84 | 10.79,29.84 C12.1 10.79,28.57 12.7,28.57 13.97,29.84 | 111.12,15.24 IC1D.7 | 131.44,15.24 IC1E.7 | 131.44,29.21 IC2E.7 | 111.12,29.21 IC2D.7 | 107.95,30.8 108.9,29.84 110.49,29.84 111.76,29.84 130.81,29.84 132.08,29.84 135.57,29.84 C15.1 135.57,30.8 107.95,30.8 | 90.81,29.21 IC2C.7 | 13.97,43.81 10.79,43.81 C13.1 10.79,42.55 12.7,42.55 13.97,43.81 | 38.1,43.81 38.73,43.18 IC3A.10 40.01,41.91 41.27,40.64 C5.2 C7.2 C4.2 C8.2 C11.2 C9.2 C6.2 C10.2 72.71,40.64 72.71,41.91 73.98,43.18 | v10.79,55.88 v13.34,55.88 38.73,55.88 41.27,53.34 v69.22,53.34 v70.48,54.61 73.66,57.78 90.17,57.78 111.76,57.78 118.75,57.78 C16.1 | 90.81,57.15 IC4C.7 | 91.44,57.78 110.49,57.78 | 111.12,56.2 111.12,57.15 C16.1 | 90.81,43.18 IC3C.7 | 74.3,43.81 90.17,43.81 91.44,43.81 107.95,43.81 111.76,43.81 118.75,43.81 123.83,43.81 | 109.22,43.81 110.49,43.81 | 133.35,43.81 123.83,43.81 | 90.81,71.12 IC5C.7 | 78.11,71.75 72.39,71.75 C17.1 | 78.11,71.75 90.17,71.75 91.44,71.75 110.49,71.75 111.76,71.75 v116.2,71.75 | 74.3,87 71.75,87 C18.1 71.75,85.72 73.03,85.72 74.3,87 | 74.3,87 90.17,87 90.81,87 91.44,87.63 93.03,87.63 | 90.81,86.36 90.81,85.41 | 111.12,71.12 IC5D.7 | 78.11,71.75 IC5C.2 | v133.99,41.91 v133.99,44.45 74.93,44.45 74.3,43.81 | 123.83,43.81 v123.83,41.91 | v111.12,101.6 110.49,100.97 v88.27,100.97 | 90.17,15.88 135.89,15.88 C14.1 | 125.73,86.68 v125.73,87.63 109.86,87.63 108.9,87.63
  Bottom 1.422: 125.73,86.68 v125.73,85.09 125.73,85.72 111.44,85.72 111.44,85.41 IC6D.7 111.12,85.41 108.9,87.63 | 125.73,86.68 111.44,86.68 | 72.07,41.59 74.3,43.81 | 42.23,41.59 40.96,41.59 38.73,43.81 | 42.23,41.59 72.07,41.59 | 38.1,43.81 38.73,43.81 | 38.73,43.81 40.01,43.81 42.23,41.59 | 90.81,85.41 IC6C.7 | 90.81,85.41 93.03,87.63 | 93.03,87.63 94.61,87.63 | 94.61,87.63 108.9,87.63 | 94.61,87.63 92.39,85.41 90.81,85.41 | 13.97,43.81 38.1,43.81 | 10.79,29.84 10.79,30.8 43.18,30.8 43.81,30.16 44.13,30.16 | 50.48,29.84 51.44,30.8 99.06,30.8 | 107.95,30.8 99.06,30.8 | 111.12,56.2 IC4D.7 | 111.12,56.2 118.75,56.2 C16.1 | 72.07,41.59 71.44,40.96
  Bottom 1.676: 60.96,87.63 73.03,99.69 v89.22,99.69 v88.27,100.97
  other vias: 18.41,73.66 17.14,74.93 18.41,76.2 17.14,77.47 18.41,78.74 20.95,78.74 19.68,77.47 20.95,76.2 19.68,74.93 20.95,73.66 33.66,77.47 34.92,76.2 32.38,76.2 95.25,113.67
  pour Bottom (isolate 0.61, no thermals): 17.14,72.07 35.88,72.07 35.88,76.83 34.29,78.42 17.78,78.42 16.51,77.15 16.51,72.71
  pour Top (isolate 0.61, no thermals): 9.84,50.48 15.24,55.56 15.24,62.23 22.23,69.85 28.57,69.85 28.57,88.58 27.62,89.53 22.23,89.53 19.05,92.71 19.05,96.52 5.08,96.52 3.81,95.25 3.81,73.66 6.99,70.8 6.99,48.9 4.45,46.35 4.45,32.38 6.99,29.84 6.99,1.91 7.62,1.27 132.08,1.27 133.67,2.86 133.67,6.35 135.25,7.94 138.75,7.94 140.02,9.53 139.7,47.31 139.7,95.89 139.38,96.2 139.38,98.42 138.43,98.42 138.43,88.58 125.41,88.58 125.41,83.19 120.02,77.47 116.52,77.47 115.89,76.83 115.89,72.07 120.33,67.63 120.33,64.77 121.28,63.82 121.28,60.96 118.43,58.1 118.43,56.52 120.02,54.93 129.86,54.93 133.99,50.8 133.99,44.45 133.67,44.13 133.67,40.01 137.48,36.2 137.48,32.38 134.62,29.53 134.62,27.62 135.89,26.35 137.48,25.08 137.48,18.41 134.62,15.24 134.62,12.7 133.35,11.43 123.83,11.43 119.7,7.3 96.84,7.3 93.03,3.49 14.29,3.81 13.97,3.81 9.84,7.94
  pour Top (isolate 0.61, no thermals): 61.91,74.61 61.91,89.53 32.07,89.53 31.11,88.58 31.11,72.39 48.9,72.39 48.9,74.61
  pour Top (no thermals): 88.9,109.22 100.33,109.22 100.33,118.11 90.17,118.11 90.17,111.76 88.9,111.76
  pour Bottom (no thermals): 65.09,79.06 60.01,79.06 59.69,79.38 59.69,87.31 60.96,88.27 62.87,89.53 63.5,89.53 63.5,86.36 65.72,84.14 65.72,79.69
  pour Bottom (no thermals): 88.27,110.17 90.17,110.17 91.12,109.22 100.33,109.22 100.33,118.11 90.17,118.11 90.17,111.76 88.9,111.76 88.27,111.12
  pour Bottom (no thermals): 108.58,43.81 108.58,41.91 111.12,41.91 111.12,43.81
  pour Bottom (no thermals): 10.79,7.62 10.79,8.89 15.88,13.97 73.03,13.97 77.79,18.73 90.49,18.73 93.34,15.88 90.81,13.34 86.36,13.34 86.04,13.65 86.04,17.46 85.41,18.1 81.28,18.1 80.64,17.46 80.64,13.65 80.33,13.34 44.45,13.34 39.69,8.57 13.97,8.57 13.02,7.62
  pour Top (isolate 0.61, no thermals): 65.41,74.93 65.41,80.64 67.63,82.87 67.63,86.36 71.75,86.36 71.75,82.55 69.85,80.64 69.85,73.03 71.75,71.12 70.48,69.85 70.48,54.61 69.53,53.66 69.53,70.8
HOME_IN  (via drill 0.6 pad 1.02)
  Top 0.356: v81.92,25.4 81.92,59.69 80.64,60.96 IC4C.12
  Bottom 0.356: IC1A.22 62.87,20.32 67.94,20.32 73.03,25.4 v81.92,25.4
MOTOR
  Top 0.813: T-1.6 31.75,97.79 32.38,98.42 65.41,98.42 76.2,109.22 T-2.4
N$1
  Top 0.356: IC1A.4 23.5,15.24 24.77,16.51 24.77,22.86 25.4,23.5 31.75,23.5 34.92,26.67 34.92,38.1 35.56,38.73 38.1,38.73 40.01,40.64 40.01,44.45 38.73,45.72 IC3A.11
N$2
  Top 0.356: IC1A.37 23.5,22.86 24.77,24.13 29.84,24.13 32.38,26.67 32.38,38.1 33.66,39.37 36.2,39.37 37.47,40.64 37.47,44.45 36.2,45.72 IC3A.12
N$3
  Top 0.356: IC1A.3 20.95,15.24 22.23,16.51 22.23,23.5 23.5,24.77 27.94,24.77 29.84,26.67 29.84,36.83 33.02,40.01 34.29,40.01 34.92,40.64 34.92,44.45 33.66,45.72 IC3A.13
N$4
  Top 0.356: IC1A.38 20.95,23.81 22.54,25.4 23.5,25.4 24.77,26.67 24.77,37.47 25.4,38.1 29.84,38.1 32.38,40.64 32.38,44.45 31.11,45.72 IC3A.14
N$5
  Top 0.356: IC1A.2 18.41,15.24 19.68,16.51 19.68,24.13 22.23,26.67 22.23,38.1 22.86,38.73 29.21,38.73 29.84,39.37 29.84,44.45 28.57,45.72 IC3A.15
N$6
  Top 0.356: IC1A.39 18.41,25.4 19.68,26.67 19.68,38.73 20.32,39.37 26.67,39.37 27.3,40.01 27.3,44.45 26.04,45.72 IC3A.16
N$7
  Top 0.356: IC1A.1 15.88,15.24 17.14,16.51 17.14,39.37 17.78,40.01 24.13,40.01 24.77,40.64 24.77,44.45 23.5,45.72 IC3A.17
N$8
  Top 0.356: IC1A.40 15.88,25.4 14.61,26.67 14.61,39.37 15.88,40.64 21.59,40.64 22.23,41.27 22.23,44.45 20.95,45.72 IC3A.18
N$9  (via drill 0.6 pad 1.02)
  Top 0.356: v65.41,24.77 65.41,26.04 64.14,27.3 64.14,31.75 62.87,33.02 IC2B.13
  Bottom 0.356: IC1A.34 31.11,22.86 32.38,24.13 57.78,24.13 58.42,24.77 61.59,24.77 62.23,24.13 64.77,24.13 v65.41,24.77
N$10  (via drill 0.6 pad 1.02)
  Top 0.356: v60.33,22.86 59.05,24.13 59.05,31.75 57.78,33.02 IC2B.15 | v13.34,21.59 13.34,39.37 IC3A.1
  Bottom 0.356: v60.33,22.86 37.47,22.86 IC1A.32 34.92,20.32 14.61,20.32 v13.34,21.59
N$11
  Top 0.356: IC2B.7 60.33,31.75 59.05,33.02 59.05,36.83 62.87,40.64 62.87,41.91 64.14,43.18 C9.1 64.14,46.99 63.5,47.62 59.69,47.62 57.78,49.53 RN4.6
N$12  (via drill 0.8 pad 1.52)
  other vias: 128.91,41.91
N$13  (via drill 0.6 pad 1.02)
  Top 0.356: v66.67,23.5 66.67,31.75 65.41,33.02 IC2B.12
  Bottom 0.356: IC1A.33 33.66,22.86 34.29,23.5 58.42,23.5 59.05,24.13 60.96,24.13 61.59,23.5 v66.67,23.5
N$15
  Top 0.356: IC1A.20 64.14,7.62 57.78,13.97 57.78,25.4 56.52,26.67 56.52,31.75 55.24,33.02 IC2B.16
N$16
  Top 0.356: IC1A.8 33.66,5.71 34.29,5.08 49.53,5.08 50.16,5.71 50.16,25.4 51.44,26.67 51.44,31.75 50.16,33.02 IC2B.18
N$17  (via drill 0.6 pad 1.02)
  Top 0.356: v53.98,26.67 53.98,31.75 52.7,33.02 IC2B.17
  Bottom 0.356: IC1A.36 26.04,22.86 28.57,25.4 39.37,25.4 40.64,26.67 v53.98,26.67
N$18  (via drill 0.6 pad 1.02)
  Top 0.356: v94.61,26.67 94.61,37.47 95.25,38.1 96.52,38.1 97.16,38.73 97.16,52.7 95.89,53.98 IC4D.1 95.89,58.42 98.42,60.96 IC4D.13 98.42,64.77 97.16,66.04 97.16,69.85 | IC1A.21 64.14,24.13 61.59,26.67 61.59,31.75 60.33,33.02 IC2B.14 | 97.16,69.85 IC5D.1 | 97.16,69.85 97.16,93.98 95.89,95.25 IC7D.1
  Bottom 0.356: IC1A.21 67.94,21.59 73.03,26.67 v94.61,26.67 114.94,26.67 IC2E.1
N$20  (via drill 0.6 pad 1.02)
  Top 0.356: v93.34,64.77 93.34,81.28 92.08,82.55 92.08,88.9 90.81,90.17 IC6C.8 | IC3D.11 103.5,50.8 107.31,54.61 v107.31,64.77
  Bottom 0.356: v107.31,64.77 v93.34,64.77
N$21  (via drill 0.8 pad 1.52)
  other vias: 121.28,41.91
N$22  (via drill 0.8 pad 1.52)
  other vias: 118.75,41.91
N$23
  Top 0.356: IC3C.9 IC4C.6
N$24
  Top 0.356: IC3C.10 85.72,53.34 87,54.61 87,59.69 85.72,60.96 IC4C.10
N$26
  Top 0.356: IC3D.12 IC3D.3
  Bottom 0.356: IC3C.8 92.08,50.8 99.69,50.8 IC3D.12
N$27  (via drill 0.7 pad 1.02)
  Top 0.356: v98.42,82.55 IC5D.13
  Bottom 0.356: v98.42,82.55 87.63,82.55 86.36,81.28 80.64,81.28 78.11,83.82 IC6C.2
N$28  (via drill 0.6 pad 1.02)
  Top 0.356: IC3D.13 98.42,53.34 97.16,54.61 97.16,58.42 99.69,60.96 99.69,81.28 v100.97,82.55 | IC6D.4 v103.5,82.55 IC5D.11
  Bottom 0.356: v100.97,82.55 v103.5,82.55
N$30
  Bottom 0.356: IC6D.2 99.69,86.36 107.31,86.36 IC6D.6
N$32  (via drill 0.6 pad 1.02)
  Top 0.356: IC3C.2 78.11,45.72 76.83,46.99 v76.83,78.74
  Bottom 0.356: v76.83,78.74 89.53,78.74 90.81,80.01 106.05,80.01 107.31,78.74 109.86,78.74 IC5D.8
N$33  (via drill 0.6 pad 1.02)
  Top 0.356: v87,50.8 87,46.99 88.27,45.72 IC3C.6
  Bottom 0.356: IC3C.13 79.38,50.8 v87,50.8
N$34  (via drill 0.6 pad 1.02)
  Top 0.356: v95.89,39.37 IC3D.1
  Bottom 0.356: IC3C.1 76.83,40.64 87,40.64 88.27,39.37 v95.89,39.37
N$35  (via drill 0.7 pad 1.02)
  Top 0.356: IC3C.12 79.38,50.8 79.38,73.66 81.92,76.2 v81.92,83.82
  Bottom 0.356: IC6D.1 94.61,83.82 v81.92,83.82
N$36  (via drill 0.6 pad 1.02)
  Top 0.356: IC6C.11 83.19,90.81 83.82,90.81 84.45,90.17 v84.45,82.55
  Bottom 0.356: v84.45,82.55 86.36,82.55 87,83.19 96.52,83.19 97.16,83.82 99.69,83.82 IC6D.3
N$37
  Bottom 0.356: IC7D.10 IC7D.9
N$38  (via drill 0.8 pad 1.52)
  other vias: 123.83,49.53
N$39  (via drill 0.8 pad 1.52)
  other vias: 126.36,49.53
N$45  (via drill 0.6 pad 1.02)
  Top 0.356: v95.89,66.04 95.89,67.31 94.61,68.58 v94.61,93.98
  Bottom 0.356: IC4C.9 88.27,64.77 89.53,66.04 v95.89,66.04 | v94.61,93.98 95.89,95.25 107.31,95.25 108.58,96.52 IC7D.6
N$46  (via drill 0.6 pad 1.02)
  Top 0.356: v73.03,64.77 73.03,92.71 78.11,97.79 89.53,97.79 92.08,100.33 99.69,100.33 100.97,101.6 IC7D.12
  Bottom 0.356: IC4C.13 76.83,64.77 v73.03,64.77
N$49  (via drill 0.6 pad 1.02)
  Top 0.356: IC1E.1 116.2,17.78 114.94,19.05 114.94,25.4 113.67,26.67 113.67,51.44 114.3,52.07 114.3,67.31 113.67,67.94 113.67,93.34 v114.3,93.8
  Bottom 0.356: v114.3,93.8 113.84,93.8 113.67,93.98 104.78,93.98 IC6D.11
N$50  (via drill 0.6 pad 1.02)
  Top 0.356: v94.61,54.61 94.61,66.67 93.98,67.31 93.98,82.55 93.34,83.19 v93.34,92.71
  Bottom 0.356: IC4C.4 84.45,54.61 v94.61,54.61 | IC6D.13 97.16,91.44 94.61,91.44 v93.34,92.71
N$51  (via drill 0.6 pad 1.02)
  Top 0.356: v120.02,11.43 120.02,17.78 121.28,19.05 IC1E.12 | v102.23,10.16 102.23,50.8 104.78,53.34 104.78,72.39 107.31,74.93 107.31,93.34 106.68,93.98 102.23,93.98 IC6D.12
  Bottom 0.356: IC1A.13 46.35,7.62 49.53,10.79 71.12,10.79 71.75,11.43 76.83,11.43 77.47,10.79 92.71,10.79 93.34,10.16 v102.23,10.16 109.86,10.16 111.12,11.43 v120.02,11.43 | IC1E.8 130.18,22.86 122.56,22.86 IC1E.12
N$52  (via drill 0.6 pad 1.02)
  Top 0.356: v128.91,24.13 IC1E.9 | v120.02,24.13 120.02,19.05 118.75,17.78 IC1E.2
  Bottom 0.356: v120.02,24.13 v128.91,24.13
N$53
  Top 0.356: IC1D.5 106.05,10.16 104.78,8.89 98.42,8.89 97.16,10.16 97.16,22.86 100.97,26.67 IC2D.3
N$54
  Bottom 0.356: IC2D.2 99.69,29.21 107.31,29.21 IC2D.6
N$55
  Bottom 0.356: IC1D.2 99.69,12.7 107.31,12.7 IC1D.6
N$56
  Bottom 0.356: IC1D.12 102.23,22.86 109.86,22.86 IC1D.8
N$57  (via drill 0.6 pad 1.02)
  Top 0.356: v111.12,38.1 IC2D.8
  Bottom 0.356: IC2D.12 100.97,36.83 102.23,38.1 v111.12,38.1
N$58
  Top 0.356: IC1D.11 103.5,22.86 107.31,26.67 107.31,31.75 108.58,33.02 IC2D.9
N$59  (via drill 0.6 pad 1.02)
  Top 0.356: v108.58,24.13 IC1D.9 | v100.97,24.13 99.69,22.86 99.69,19.05 100.97,17.78 IC1D.3
  Bottom 0.356: v100.97,24.13 v108.58,24.13
N$60
  Bottom 0.356: IC1E.13 118.75,25.4 120.02,26.67 127.64,26.67 IC2E.6
N$61  (via drill 0.6 pad 1.02, 0.8 pad 1.52)
  Top 0.356: IC1E.11 123.83,25.4 125.09,26.67 125.09,30.48 127.64,33.02 127.64,36.83 131.44,40.64 v131.44,41.91 131.44,45.72 130.18,46.99 v130.18,52.07 | IC2D.5 106.05,31.75 107.31,33.02 v107.31,39.37
  Bottom 0.356: v107.31,39.37 130.18,39.37 131.44,40.64 v131.44,41.91 | IC4C.3 80.64,54.61 81.92,53.34 92.71,53.34 93.34,52.7 114.3,52.7 114.94,53.34 128.91,53.34 v130.18,52.07
N$63  (via drill 0.6 pad 1.02)
  Top 0.356: v99.69,54.61 99.69,59.69 100.97,60.96 IC4D.12 100.97,67.31 102.23,68.58 102.23,87.63 106.05,91.44 IC6D.10
  Bottom 0.356: IC4D.5 104.78,54.61 v99.69,54.61
N$64  (via drill 0.6 pad 1.02)
  Top 0.356: v109.86,54.61 109.86,64.77 106.05,68.58 IC5D.5
  Bottom 0.356: IC4D.2 98.42,53.98 99.06,53.34 108.58,53.34 v109.86,54.61
N$65  (via drill 0.6 pad 1.02, 0.7 pad 1.02, 0.8 pad 1.52)
  Top 0.356: v114.94,40.64 v114.94,50.8 | v94.61,17.78 94.61,24.13 95.89,25.4 IC2D.1 95.89,30.48 98.42,33.02 IC2D.13 | IC1D.4 v103.5,17.78 106.05,20.32 IC1D.10 | v116.2,92.71 114.94,92.71 114.3,92.08 114.3,71.12 116.2,69.22 116.2,67.94 115.57,67.31 115.57,53.98 116.2,53.34 126.36,53.34 128.91,50.8 v128.91,49.53
  Bottom 0.356: IC2D.13 98.42,36.83 100.97,39.37 104.78,39.37 106.05,40.64 v114.94,40.64 | IC4C.1 75.56,54.61 78.11,52.07 91.44,52.07 92.08,51.44 114.3,51.44 v114.94,50.8 127.64,50.8 v128.91,49.53 | v94.61,17.78 v103.5,17.78 | v116.2,92.71 IC6D.8
N$66
  Top 0.356: IC3A.9 36.2,44.45 34.92,45.72 34.92,50.8 36.2,52.07 RN2.8
N$67  (via drill 0.6 pad 1.02)
  Top 0.356: IC1E.3 121.28,17.78 122.56,19.05 122.56,25.4 121.28,26.67 IC2E.3 121.28,31.75 122.56,33.02 v122.56,52.07
  Bottom 0.356: IC4C.2 78.11,54.61 80.01,52.7 92.08,52.7 92.71,52.07 v122.56,52.07
N$70
  Bottom 0.356: IC1A.24 56.52,20.32 57.15,19.68 68.58,19.68 73.03,24.13 83.19,24.13 84.45,25.4 98.42,25.4 99.06,26.04 118.11,26.04 118.75,26.67 IC2E.2
N$71  (via drill 0.6 pad 1.02)
  Top 0.356: v99.69,40.64 99.69,50.8 100.97,52.07 IC4D.3 100.97,59.69 102.23,60.96 102.23,62.23 IC4D.11
  Bottom 0.356: IC3D.4 102.23,40.64 v99.69,40.64
N$72  (via drill 0.6 pad 1.02)
  Top 0.356: IC6C.5 85.72,88.9 87,90.17 v87,93.98
  Bottom 0.356: v87,93.98 89.53,93.98 91.44,95.89 102.87,95.89 103.5,96.52 IC7D.4
N$73  (via drill 0.6 pad 1.02)
  Top 0.356: IC6C.6 88.27,83.82 89.53,82.55 89.53,76.2 88.27,74.93 v88.27,73.66 | v98.42,73.66 IC5D.2
  Bottom 0.356: v88.27,73.66 v98.42,73.66
N$74
  Top 0.356: IC4D.8 111.12,64.77 109.86,66.04 109.86,88.9 108.58,90.17 IC6D.9
N$76
  Top 0.356: IC3A.8 33.66,44.45 32.38,45.72 32.38,54.61 36.2,58.42 RN1.8
N$77
  Top 0.356: IC3A.7 31.11,44.45 29.84,45.72 29.84,50.8 31.11,52.07 RN2.6
N$78
  Top 0.356: IC3A.6 28.57,44.45 27.3,45.72 27.3,54.61 31.11,58.42 RN1.6
N$79  (via drill 0.6 pad 1.02)
  Top 0.356: IC6C.3 80.64,88.9 81.92,90.17 v81.92,95.25
  Bottom 0.356: v81.92,95.25 89.53,95.25 90.81,96.52 97.16,96.52 IC7D.2
N$80
  Top 0.356: IC3A.5 26.04,44.45 24.77,45.72 24.77,50.8 26.04,52.07 RN2.4
N$81
  Top 0.356: IC3A.4 23.5,44.45 22.23,45.72 22.23,54.61 26.04,58.42 RN1.4
N$82
  Top 0.356: IC3A.3 20.95,44.45 19.68,45.72 19.68,50.8 20.95,52.07 RN2.2
N$83
  Top 0.356: IC3A.2 18.41,44.45 17.14,45.72 17.14,54.61 20.95,58.42 RN1.2
N$84
  Top 0.356: IC2B.6 57.78,31.75 56.52,33.02 56.52,38.1 59.05,40.64 59.05,41.91 60.33,43.18 C11.1 60.33,46.99 59.05,46.99 56.52,49.53 56.52,54.61 57.78,55.88 RN3.6
N$85
  Top 0.356: IC2B.9 65.41,31.75 64.14,33.02 64.14,36.83 65.41,38.1 69.22,38.1 70.48,39.37 70.48,41.91 71.75,43.18 C10.1 71.75,46.99 69.85,48.9 61.59,48.9 60.33,50.16 RN4.7
N$87
  Top 0.356: IC2B.5 55.24,31.75 53.98,33.02 53.98,41.91 56.52,44.45 C8.1 56.52,46.99 55.24,48.26 53.98,48.26 52.7,49.53 RN4.4
N$88
  Top 0.356: IC2B.3 50.16,31.75 48.9,33.02 48.9,36.83 47.62,38.1 47.62,41.91 48.9,43.18 C7.1 48.9,46.99 47.62,48.26 RN4.2
N$89
  Top 0.356: IC2B.8 62.87,31.75 61.59,33.02 61.59,36.83 64.14,39.37 65.41,39.37 66.67,40.64 66.67,41.91 67.94,43.18 C6.1 67.94,46.99 66.67,48.26 60.33,48.26 59.05,49.53 59.05,52.07 62.87,55.88 RN3.8
N$90
  Top 0.356: IC2B.2 47.62,31.75 46.35,33.02 46.35,41.91 45.09,43.18 C5.1 45.09,46.99 43.81,48.26 43.81,52.07 47.62,55.88 RN3.2
N$101  (via drill 0.6 pad 1.02)
  Top 0.356: v41.27,25.4 v41.27,50.8 | v69.22,25.4 69.22,34.29 IC2B.11
  Bottom 0.356: IC1A.35 28.57,22.86 30.48,24.77 40.64,24.77 v41.27,25.4 41.91,24.77 57.15,24.77 58.42,26.04 68.58,26.04 v69.22,25.4 | v41.27,50.8 19.68,50.8 IC3A.19
PHI
  Top 0.356: IC2B.4 52.7,31.75 51.44,33.02 51.44,41.91 52.7,43.18 C4.1 52.7,46.99 51.44,48.26 50.16,48.26 48.9,49.53 48.9,53.34 51.44,55.88 51.44,60.96 RN5.4 50.16,63.5 53.98,67.31 T-5.19
RDDT  (via drill 0.6 pad 1.02)
  Top 0.356: v109.86,96.52 109.86,99.06 109.22,99.69 101.6,99.69 100.97,99.06 IC7D.3 | R1.1 118.11,87 126.36,95.25 T-4.5
  Bottom 0.356: T-4.5 126.36,96.52 125.09,95.25 115.57,95.25 114.3,96.52 v109.86,96.52
READ
  Top 0.813: T-1.2 21.59,93.98 24.13,91.44 36.83,91.44 38.1,92.71 69.85,92.71 86.36,109.22 T-2.8
RESET
  Top 0.356: RN3.5 RN5.6 55.24,63.5 56.52,64.77 T-5.21
S0
  Top 0.356: RN4.5 55.24,54.61 56.52,55.88 56.52,59.69 57.78,60.96 RN5.7 57.78,71.12 T-5.22
S1
  Top 0.356: RN3.7 RN5.8 60.33,66.04 59.05,67.31 T-5.23
SENSE
  Top 0.813: T-1.5 29.21,95.25 30.48,93.98 33.02,93.98 35.56,96.52 66.04,96.52 78.74,109.22 T-2.5
VCC  (via drill 0.6 pad 1.02, 0.7 pad 1.02, 0.8 pad 1.52)
  Top 0.61: IC1D.14 IC1D.1
  Top 0.813: v36.2,16.51 IC1A.9 | v80.64,47.62 IC3C.3 | v116.2,49.53 v116.2,41.91 | v126.36,46.99 v126.36,41.91 | v95.89,90.17 IC6D.14 | v132.08,92.08 135.25,92.08 135.89,92.71 135.89,96.84 T-4.9 136.53,92.71 135.25,91.44 v130.81,91.44 | IC1E.4 123.83,16.51 126.36,19.05 IC1E.10 | v123.83,33.02 IC2E.4 | IC2D.4 103.5,31.11 106.05,33.66 IC2D.10 | v103.5,60.96 IC4D.4 | v103.5,74.93 IC5D.4
  Top 1.016: v135.25,103.5 135.25,104.14 136.53,104.14 v136.53,102.23
  Top 1.27: T-4.9 v136.53,102.23 v135.25,103.5
  Bottom 0.813: T-4.9 136.53,83.82 134.94,82.23 v133.99,81.28 C2.1 127.64,75.56 127.64,62.23 | 95.89,20.32 96.52,19.68 98.42,19.68 | 98.42,19.68 115.57,19.68 116.2,20.32 116.84,19.68 126.36,19.68 135.89,19.68 C14.2 137.79,19.68 139.06,19.68 | 95.89,20.32 IC1D.14 IC1D.13 98.42,19.68 | 95.89,20.32 95.25,19.68 93.66,19.68 | 10.79,16.51 v36.2,16.51 73.03,17.14 | 10.79,16.51 C1.2 | 8.26,16.51 10.79,16.51 | 8.26,16.51 8.26,34.29 | 8.26,34.29 C12.2 11.43,33.66 | 135.89,33.66 C15.2 139.06,34.29 | 116.84,33.66 116.2,34.29 115.57,33.66 | 96.52,33.66 95.89,34.29 95.25,33.66 | 76.2,33.66 75.56,34.29 74.93,33.66 | 45.72,33.66 45.09,34.29 44.45,33.66 | 8.26,48.26 C13.2 11.43,47.62 | 8.26,34.29 8.26,48.26 | 74.93,47.62 75.56,48.26 76.2,47.62 | 95.89,48.26 96.52,47.62 | 115.57,47.62 116.2,48.26 116.84,47.62 | 139.06,19.68 139.06,34.29 | 139.06,19.68 139.06,12.7 138.11,11.43 124.14,11.43 116.52,3.81 9.53,3.81 8.26,5.08 8.26,16.51 | 8.26,48.26 8.26,58.42 13.34,63.5 13.34,82.55 18.41,87.63 26.67,87.63 | 74.93,61.59 75.56,62.23 | 75.56,62.23 IC4C.14 | 75.56,62.23 76.2,61.59 | 95.25,61.59 95.89,62.23 96.52,61.59 | 118.11,61.59 C16.2 127.64,62.23 | 139.06,34.29 139.06,52.07 128.91,62.23 127.64,62.23 | 72.39,75.56 C17.2 69.22,76.2 | 75.56,76.2 74.93,75.56 | 75.56,76.2 IC5C.14 | 76.2,75.56 75.56,76.2 | 95.25,75.56 95.89,76.2 96.52,75.56 | 72.39,90.81 C18.2 70.48,91.44 69.22,90.17 69.22,76.2 | 74.93,90.81 75.56,91.44 | 75.56,91.44 IC6C.14 | 75.56,91.44 76.2,90.81 | 26.67,87.63 X-TAL.14 52.7,87.63 | 52.7,87.63 68.58,103.5 81.28,103.5 | 81.28,103.5 95.25,103.5 | 95.25,103.5 95.89,104.14 | 95.89,104.14 IC7D.14 | 95.89,104.14 96.52,103.5 95.25,103.5
  Bottom 0.813: 52.7,87.63 52.7,83.82 56.52,80.01 56.52,76.2 62.87,76.2 64.14,74.93 | 64.14,74.93 64.14,69.85 T-5.25 | 64.14,74.93 65.41,76.2 69.22,76.2 | IC3C.3 IC3C.4 | 126.36,47.62 v126.36,46.99 | 123.83,33.66 v123.83,33.02 | 103.5,61.59 v103.5,60.96 | 103.5,75.56 v103.5,74.93 | 81.28,103.5 81.28,106.68 T-2.6 | 26.67,87.63 T-1.4
  Bottom 1.016: v133.99,81.28 C3.+ | v136.53,102.23 136.53,104.14 131.76,104.14 130.81,103.19 | 80.01,105.41 81.28,106.68 82.55,105.41 | IC6C.14 75.56,92.39 76.83,91.12
  Bottom 1.27: v136.53,102.23 v135.25,103.5
  Bottom 1.422: 116.2,20.32 IC1E.14 | 76.52,20.64 92.71,20.64 | 92.71,20.64 93.66,19.68 94.61,19.68 | 73.03,17.14 76.52,20.64 | 135.89,33.66 123.83,33.66 116.84,33.66 115.57,33.66 106.05,33.66 | 116.2,34.29 IC2E.14 | 106.05,33.66 96.52,33.66 95.25,33.66 76.2,33.66 74.93,33.66 45.72,33.66 44.45,33.66 15.88,33.66 | 95.89,34.29 IC2D.14 | 75.56,34.29 IC2C.14 | 45.09,34.29 IC2B.20 | 11.43,33.66 15.88,33.66 | 15.88,33.66 IC2A.20 | 11.43,47.62 15.88,47.62 | 15.88,47.62 IC3A.20 | 15.88,47.62 74.93,47.62 76.2,47.62 v80.64,47.62 95.25,47.62 | 75.56,48.26 IC3C.14 | 95.25,47.62 95.89,48.26 IC3D.14 | 116.2,48.26 v116.2,49.53 | 131.44,47.62 126.36,47.62 116.84,47.62 115.57,47.62 96.52,47.62 95.25,47.62 | 42.55,58.42 RN5.1 | 8.26,58.42 42.55,58.42 | 42.55,58.42 42.55,55.88 67.31,55.88 73.03,61.59 74.93,61.59 76.2,61.59 95.25,61.59 96.52,61.59 103.5,61.59 106.05,61.59 | 95.89,62.23 IC4D.14 | 118.11,61.59 106.05,61.59 | 72.39,75.56 74.93,75.56 76.2,75.56 95.25,75.56 96.52,75.56 103.5,75.56 106.05,75.56 | 95.89,76.2 IC5D.14 | 127.64,75.56 106.05,75.56 | 72.39,90.81 74.93,90.81 76.2,90.81 92.71,90.81 93.34,90.17 v95.89,90.17 99.06,90.17 99.69,90.81 118.11,90.81 | 126.36,19.68 IC1E.10 | 106.05,33.66 IC2D.10 | 131.44,47.62 v131.44,49.53 | 118.11,90.81 123.19,90.81 123.83,91.44 | 123.83,91.44 v130.81,91.44 v132.08,92.08 | 106.05,61.59 IC4D.10 | 106.05,75.56 IC5D.10 | 96.52,103.5 126.36,103.5 127.64,102.23 130.18,102.23 | v136.53,102.23 130.18,102.23 | 137.79,19.68 126.36,19.68 | 131.44,47.62 136.53,47.62 | v135.25,103.5 131.44,103.5 130.18,102.23 | 76.52,20.64 77.15,21.27 92.08,21.27 | 92.71,20.64 92.08,21.27 | 92.08,21.27 93.03,21.27 94.61,19.68
  Bottom 1.422: 126.36,19.68 94.61,19.68 | 123.83,91.44 118.75,91.44 118.11,90.81 | 134.94,81.92 134.94,82.23 127.64,82.23 126.36,80.96
  pour Bottom (isolate 0.61, no thermals): 35.88,80.33 41.27,74.93 57.15,74.93 58.74,76.52 58.74,76.83 57.15,78.42 57.15,88.9 66.04,97.79 66.36,97.79 71.12,102.87 96.2,103.19 96.2,103.5 95.89,105.41 67.63,105.09 56.2,94.3 5.4,94.3 3.81,92.71 3.81,73.66 6.99,70.8 6.99,48.9 4.45,46.35 4.45,32.38 6.67,29.53 6.67,1.91 7.3,1.27 132.08,1.27 133.67,2.86 133.67,6.35 135.25,7.94 138.75,7.94 140.02,9.53 139.7,92.71 136.84,96.52 136.84,97.79 136.53,97.79 136.53,82.87 134.3,80.64 133.99,80.64 133.35,81.28 126.36,81.28 125.73,80.64 117.47,80.64 112.39,75.56 117.16,75.56 117.16,73.98 117.47,73.66 118.43,72.39 118.43,66.04 117.79,65.41 115.57,65.41 115.57,61.59 115.89,61.28 121.6,61.28 121.92,60.96 121.92,55.24 122.24,54.93 133.35,54.93 136.21,52.07 136.21,37.15 133.03,33.97 136.21,33.34 137.79,32.07 137.79,22.23 136.84,21.27 134.62,21.27 133.67,20.32 133.67,19.68 136.21,19.68 137.79,17.78 137.79,13.02 136.21,11.43 123.83,11.43 119.7,7.3 100.01,7.3 96.52,3.81 10.48,3.81 8.89,5.4 8.89,10.48 10.79,12.7 arc-9 11.11,13.02 12.38,13.02 14.92,15.56 71.75,15.56 73.34,17.14 12.7,17.14 10.79,19.05 10.79,25.4 8.57,27.62 8.57,32.38 9.53,33.34 13.02,33.34 13.02,33.66 17.46,33.66 17.46,33.97 15.88,35.56 9.21,35.56 8.57,36.2 8.57,46.67 9.21,47.31 17.78,47.31 15.88,49.21 13.02,49.21 8.89,53.34 8.89,57.47 9.53,58.1 16.19,58.1 16.19,70.17 14.92,71.44 14.92,78.74 16.51,80.33
  pour Bottom (isolate 0.61, no thermals): 57.15,77.15 66.67,77.15 67.63,78.11 67.63,91.44 69.22,93.03 75.56,93.03 75.88,92.71 75.88,90.49 70.48,90.49 69.85,89.85 69.85,78.74 70.48,78.11 75.25,78.11 75.88,77.47 75.88,75.25 67.63,75.25 66.04,73.66 66.04,67.31 69.53,63.5 75.56,63.5 75.88,63.18 75.88,61.59 73.03,61.59 68.26,56.83 68.26,60.64 65.09,60.64 65.09,66.36 61.59,69.85 62.87,69.85 63.5,70.48 63.5,73.98 62.55,74.93 57.15,74.93
  pour Bottom (no thermals): 95.89,19.68 99.06,19.68 99.06,22.23 95.25,22.23 95.25,20.32
WRGA
  Bottom 0.356: IC6C.12 80.64,96.52 81.92,97.79 89.53,97.79 91.44,99.69 113.03,99.69 113.67,100.5 120.02,100.5 121.28,99.06 T-4.3
WRITE
  Top 0.813: T-1.3 24.13,93.98 25.4,92.71 34.92,92.71 36.83,94.61 69.22,94.61 83.82,109.22 T-2.7

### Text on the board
Bottom: MITSUMI ELEC.CO | QD-SIO-3
tPlace: 1 | 9 | 1 | 10 | 1 | 6 | 2 | 26 | 1 | 25
tValues: Version 20120627 | QD-SIO-3 | SHARP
